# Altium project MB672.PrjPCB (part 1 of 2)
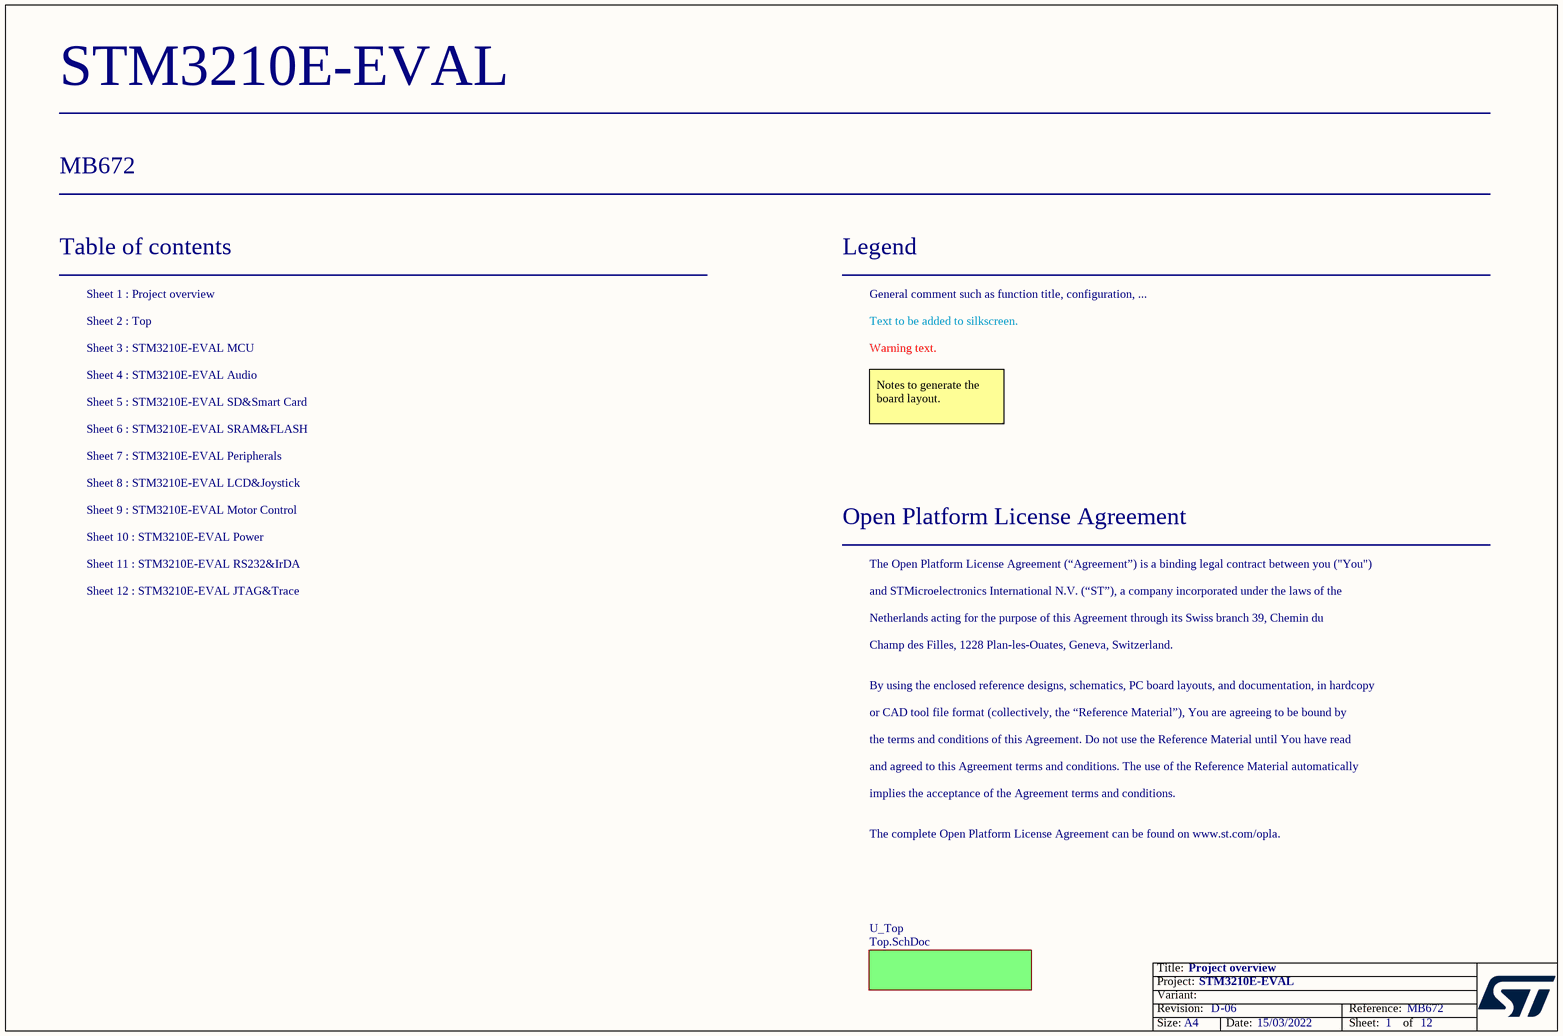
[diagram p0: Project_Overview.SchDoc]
Board_Reference: MB672; Board_PCB_Revision: D; Board_Name: STM3210E-EVAL; Board_Document_Date: 15/03/2022; Board_Assembly_Revision: 06
12 sheets, 357 parts. Net scope: flat (ports and power ports of the same name join across sheets).
Board file: MB672.PCBDOC
Sheets:
  Project_Overview.SchDoc
    U_Top = Top.SchDoc
      U_Audio = Audio.SchDoc
      U_SRAM&Flash = SRAM&Flash.SchDoc
      U_RS232&IrDA = RS232&IrDA.SchDoc
      U_Peripherals = Peripherals.SchDoc
      U_MotorCtrl = MotorCtrl.SchDoc
      U_Power = Power.SchDoc
      U_JTAG&SWD = JTAG&SWD.SchDoc
      U_MCU = MCU.SchDoc
      U_SD&Smart_Card = SD&Smart_Card.SchDoc
      U_LCD&Joystick = LCD&Joystick.SchDoc

## Sheet Project_Overview.SchDoc: Project overview
size A4; Date: Not used; ApprovedBy: Not used; CheckedBy: Not used; Author: Not used; CompanyName: STMicroelectronics; DrawnBy: Not used; Engineer: Not used; Organization: Not used; Address1: Not used; Address2: Not used; Address3: Not used; Address4: Not used; DocumentNumber: Not used; Revision: Not used; SheetNumber: 1; SheetTotal: 12

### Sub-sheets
U_Top = Top.SchDoc: no entries

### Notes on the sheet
- STM3210E-EVAL
- MB672
- Table of contents
- Sheet 1 : Project overview
- Legend
- General comment such as function title, configuration, ...
- Sheet 2 : Top
- Sheet 3 : STM3210E-EVAL MCU
- Sheet 4 : STM3210E-EVAL Audio
- Text to be added to silkscreen.
- Warning text.
- Sheet 6 : STM3210E-EVAL SRAM&FLASH
- Sheet 5 : STM3210E-EVAL SD&Smart Card
- Notes to generate the board layout.
- Sheet 7 : STM3210E-EVAL Peripherals
- Sheet 8 : STM3210E-EVAL LCD&Joystick
- Sheet 9 : STM3210E-EVAL Motor Control
- Sheet 10 : STM3210E-EVAL Power
- Sheet 11 : STM3210E-EVAL RS232&IrDA
- Open Platform License Agreement
- The Open Platform License Agreement (“Agreement”) is a binding legal contract between you ("You")
- Sheet 12 : STM3210E-EVAL JTAG&Trace
- and STMicroelectronics International N.V. (“ST”), a company incorporated under the laws of the
- Netherlands acting for the purpose of this Agreement through its Swiss branch 39, Chemin du
- Champ des Filles, 1228 Plan-les-Ouates, Geneva, Switzerland.
- By using the enclosed reference designs, schematics, PC board layouts, and documentation, in hardcopy
- or CAD tool file format (collectively, the “Reference Material”), You are agreeing to be bound by
- the terms and conditions of this Agreement. Do not use the Reference Material until You have read
- and agreed to this Agreement terms and conditions. The use of the Reference Material automatically
- implies the acceptance of the Agreement terms and conditions.
- The complete Open Platform License Agreement can be found on www.st.com/opla.

## Sheet Top.SchDoc: STM3210E-EVAL
size A3; Date: Not used; ApprovedBy: Not used; CheckedBy: Not used; Author: Not used; CompanyName: STMicroelectronics; DrawnBy: Not used; Engineer: Not used; Organization: Not used; Address1: Not used; Address2: Not used; Address3: Not used; Address4: Not used; DocumentNumber: Not used; Revision: Not used; SheetNumber: 2; SheetTotal: 12
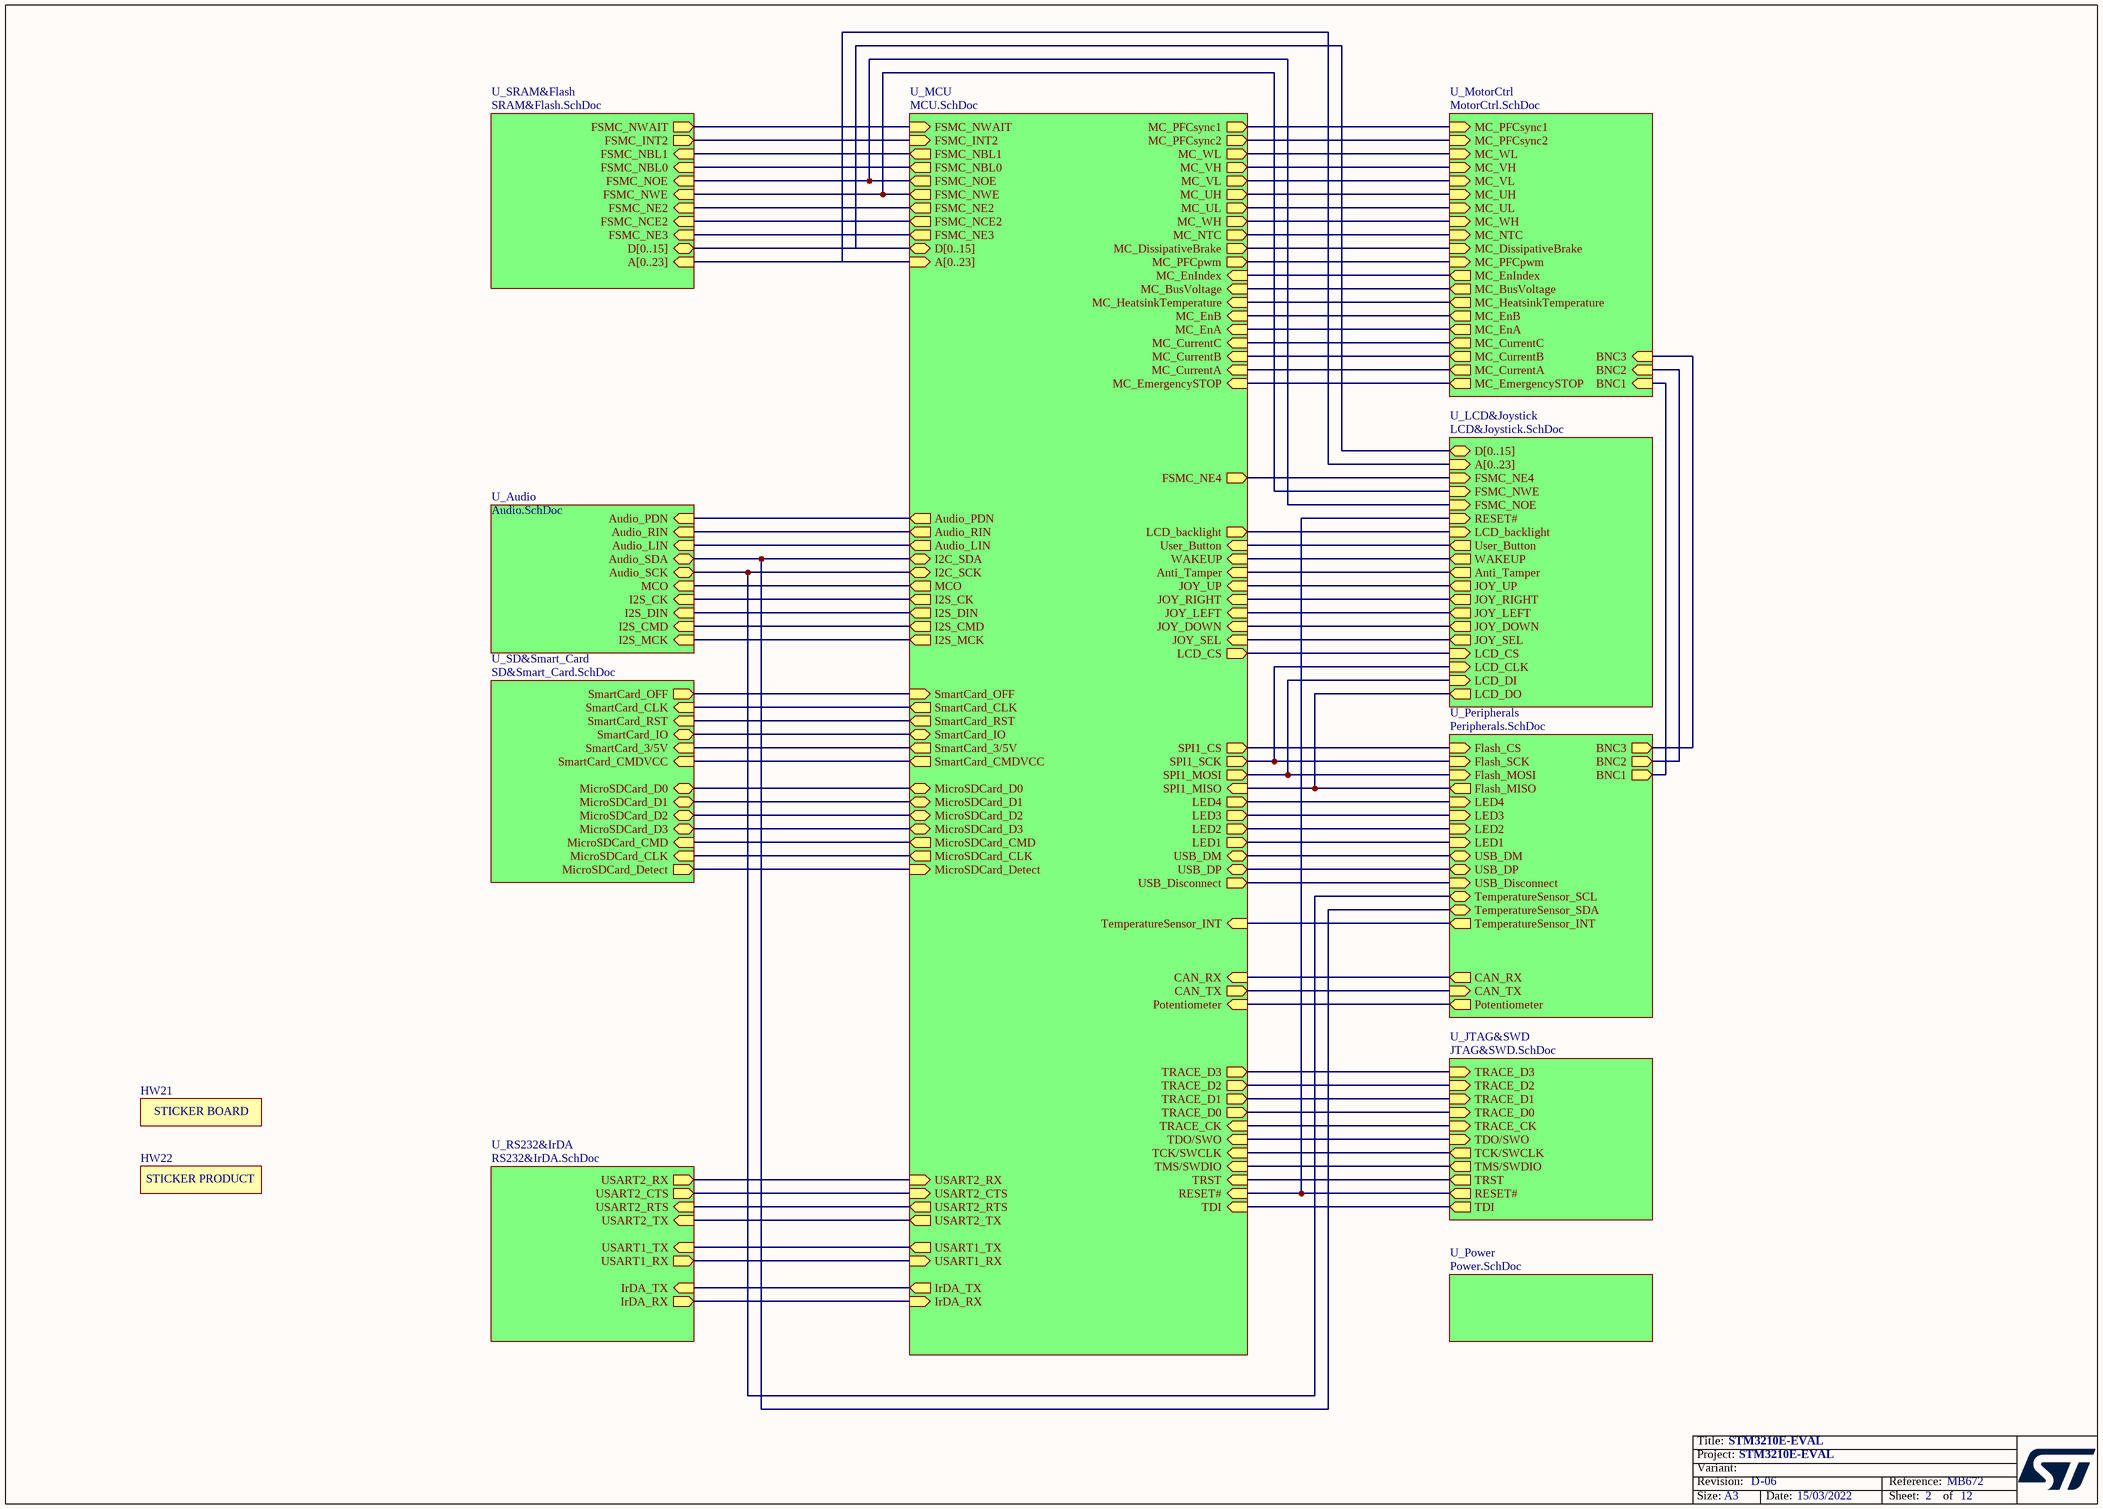
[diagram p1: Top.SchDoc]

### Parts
HW21  STICKER_BOARD  (value not drawn)  (no BOM)
HW22  STICKER_PRODUCT  (value not drawn)  (no BOM)

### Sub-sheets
U_Audio = Audio.SchDoc: I2S_CMD (in), I2S_DIN (in), I2S_CK (in), MCO (in), Audio_SCK (bidir), Audio_SDA (bidir), Audio_LIN (in), Audio_RIN (in), I2S_MCK (in), Audio_PDN (in)
U_JTAG&SWD = JTAG&SWD.SchDoc: TDI (out), RESET# (out), TRACE_D3 (in), TRACE_D2 (in), TRACE_D1 (in), TRACE_D0 (in), TRACE_CK (in), TRST (out), TMS/SWDIO (out), TCK/SWCLK (out), TDO/SWO (in)
U_LCD&Joystick = LCD&Joystick.SchDoc: JOY_SEL (out), JOY_DOWN (out), JOY_LEFT (out), JOY_RIGHT (out), JOY_UP (out), LCD_CS (in), LCD_CLK (in), LCD_DI (in), RESET# (in), LCD_backlight (in), Anti_Tamper (out), WAKEUP (out), User_Button (out), FSMC_NE4 (in), D[0..15] (bidir), A[0..23] (in), FSMC_NWE (in), FSMC_NOE (in), LCD_DO (out)
U_MCU = MCU.SchDoc: TDI (in), TRACE_CK (in), TMS/SWDIO (in), TCK/SWCLK (in), TDO/SWO (in), USART2_RX (in), USART2_TX (out), USART2_RTS (out), USART2_CTS (in), USART1_TX (out), USART1_RX (in), IrDA_RX (in), IrDA_TX (out), MC_EmergencySTOP (in), MC_CurrentA (in), MC_CurrentB (in), MC_CurrentC (in), MC_PFCsync1 (out), MC_PFCsync2 (out), MC_WL (out), MC_VH (out), MC_VL (out), MC_UH (out), MC_UL (out), MC_WH (out), MC_NTC (out), MC_DissipativeBrake (out), MC_PFCpwm (out), MC_EnA (in), MC_EnB (in), MC_HeatsinkTemperature (in), MC_BusVoltage (in), MC_EnIndex (in), JOY_SEL (in), JOY_DOWN (in), JOY_LEFT (in), JOY_RIGHT (in), JOY_UP (in), LCD_CS (out), LCD_backlight (out), Anti_Tamper (in), WAKEUP (in), User_Button (in), SPI1_CS (out), SPI1_SCK (out), SPI1_MISO (in), SPI1_MOSI (out), LED4 (out), LED3 (out), LED1 (out), LED2 (out), USB_DM (bidir), USB_DP (bidir), USB_Disconnect (out), TemperatureSensor_INT (in), CAN_TX (out), CAN_RX (in), Potentiometer (in), FSMC_NE3 (out), A[0..23] (in), D[0..15] (bidir), FSMC_NE4 (out), FSMC_NCE2 (out), FSMC_NE2 (out), FSMC_NWE (out), FSMC_NOE (out), FSMC_NBL0 (out), FSMC_NBL1 (out), FSMC_NWAIT (in), FSMC_INT2 (in), MicroSDCard_CLK (out), MicroSDCard_CMD (out), SmartCard_3/5V (out), SmartCard_IO (bidir), SmartCard_RST (out), SmartCard_CLK (out), SmartCard_OFF (in), SmartCard_CMDVCC (out), MicroSDCard_D0 (bidir), I2S_CMD (out), I2S_DIN (out), I2S_CK (out), MCO (out), I2C_SCK (bidir), I2C_SDA (bidir), MicroSDCard_D1 (bidir), MicroSDCard_D2 (bidir), MicroSDCard_D3 (bidir), RESET# (in), TRACE_D3 (out), TRACE_D2 (out), TRACE_D1 (out), TRACE_D0 (out), TRST (in), Audio_LIN (out), Audio_RIN (out), MicroSDCard_Detect (in), I2S_MCK (out), Audio_PDN (out)
U_MotorCtrl = MotorCtrl.SchDoc: MC_EmergencySTOP (out), MC_CurrentA (out), MC_CurrentB (out), MC_CurrentC (out), MC_PFCsync1 (in), MC_PFCsync2 (in), MC_WL (in), MC_VH (in), MC_VL (in), MC_UH (in), MC_UL (in), MC_WH (in), MC_NTC (in), MC_DissipativeBrake (in), MC_PFCpwm (in), MC_EnA (out), MC_EnB (out), MC_HeatsinkTemperature (out), MC_BusVoltage (out), MC_EnIndex (out), BNC1 (in), BNC2 (in), BNC3 (in)
U_Peripherals = Peripherals.SchDoc: Flash_CS (in), Flash_SCK (in), Flash_MISO (out), Flash_MOSI (in), LED4 (in), LED3 (in), LED1 (in), LED2 (in), USB_DM (bidir), USB_DP (bidir), USB_Disconnect (in), TemperatureSensor_INT (out), TemperatureSensor_SCL (bidir), TemperatureSensor_SDA (bidir), BNC1 (out), CAN_TX (in), CAN_RX (out), Potentiometer (out), BNC2 (out), BNC3 (out)
U_Power = Power.SchDoc: no entries
U_RS232&IrDA = RS232&IrDA.SchDoc: USART2_RX (out), USART2_TX (in), USART2_RTS (in), USART2_CTS (out), USART1_TX (in), USART1_RX (out), IrDA_RX (out), IrDA_TX (in)
U_SD&Smart_Card = SD&Smart_Card.SchDoc: MicroSDCard_CLK (in), MicroSDCard_CMD (in), SmartCard_3/5V (in), SmartCard_IO (bidir), SmartCard_RST (in), SmartCard_CLK (in), SmartCard_OFF (out), SmartCard_CMDVCC (in), MicroSDCard_D0 (bidir), MicroSDCard_D1 (bidir), MicroSDCard_D2 (bidir), MicroSDCard_D3 (bidir), MicroSDCard_Detect (out)
U_SRAM&Flash = SRAM&Flash.SchDoc: A[0..23] (in), D[0..15] (bidir), FSMC_NE3 (in), FSMC_NCE2 (in), FSMC_NE2 (in), FSMC_NWE (in), FSMC_NOE (in), FSMC_NBL0 (in), FSMC_NBL1 (in), FSMC_NWAIT (out), FSMC_INT2 (out)

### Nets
(unnamed): sheet U_Audio/I2S_CMD, sheet U_MCU/I2S_CMD
(unnamed): sheet U_Audio/I2S_DIN, sheet U_MCU/I2S_DIN  [a separate net that carries the same name]
(unnamed): sheet U_Audio/I2S_CK, sheet U_MCU/I2S_CK  [a separate net that carries the same name]
(unnamed): sheet U_Audio/MCO, sheet U_MCU/MCO  [a separate net that carries the same name]
(unnamed): sheet U_Audio/Audio_SCK, sheet U_Peripherals/TemperatureSensor_SCL, sheet U_MCU/I2C_SCK  [a separate net that carries the same name]
(unnamed): sheet U_Audio/Audio_SDA, sheet U_Peripherals/TemperatureSensor_SDA, sheet U_MCU/I2C_SDA  [a separate net that carries the same name]
(unnamed): sheet U_Audio/Audio_LIN, sheet U_MCU/Audio_LIN  [a separate net that carries the same name]
(unnamed): sheet U_Audio/Audio_RIN, sheet U_MCU/Audio_RIN  [a separate net that carries the same name]
(unnamed): sheet U_Audio/I2S_MCK, sheet U_MCU/I2S_MCK  [a separate net that carries the same name]
(unnamed): sheet U_Audio/Audio_PDN, sheet U_MCU/Audio_PDN  [a separate net that carries the same name]
(unnamed): sheet U_SRAM&Flash/FSMC_NE3, sheet U_MCU/FSMC_NE3  [a separate net that carries the same name]
(unnamed): sheet U_SRAM&Flash/FSMC_NCE2, sheet U_MCU/FSMC_NCE2  [a separate net that carries the same name]
(unnamed): sheet U_SRAM&Flash/FSMC_NE2, sheet U_MCU/FSMC_NE2  [a separate net that carries the same name]
(unnamed): sheet U_SRAM&Flash/FSMC_NWE, sheet U_MCU/FSMC_NWE, sheet U_LCD&Joystick/FSMC_NWE  [a separate net that carries the same name]
(unnamed): sheet U_SRAM&Flash/FSMC_NOE, sheet U_MCU/FSMC_NOE, sheet U_LCD&Joystick/FSMC_NOE  [a separate net that carries the same name]
(unnamed): sheet U_SRAM&Flash/FSMC_NBL0, sheet U_MCU/FSMC_NBL0  [a separate net that carries the same name]
(unnamed): sheet U_SRAM&Flash/FSMC_NBL1, sheet U_MCU/FSMC_NBL1  [a separate net that carries the same name]
(unnamed): sheet U_SRAM&Flash/FSMC_NWAIT, sheet U_MCU/FSMC_NWAIT  [a separate net that carries the same name]
(unnamed): sheet U_SRAM&Flash/FSMC_INT2, sheet U_MCU/FSMC_INT2  [a separate net that carries the same name]
(unnamed): sheet U_RS232&IrDA/USART2_RX, sheet U_MCU/USART2_RX  [a separate net that carries the same name]
(unnamed): sheet U_RS232&IrDA/USART2_TX, sheet U_MCU/USART2_TX  [a separate net that carries the same name]
(unnamed): sheet U_RS232&IrDA/USART2_RTS, sheet U_MCU/USART2_RTS  [a separate net that carries the same name]
(unnamed): sheet U_RS232&IrDA/USART2_CTS, sheet U_MCU/USART2_CTS  [a separate net that carries the same name]
(unnamed): sheet U_RS232&IrDA/USART1_TX, sheet U_MCU/USART1_TX  [a separate net that carries the same name]
(unnamed): sheet U_RS232&IrDA/USART1_RX, sheet U_MCU/USART1_RX  [a separate net that carries the same name]
(unnamed): sheet U_RS232&IrDA/IrDA_RX, sheet U_MCU/IrDA_RX  [a separate net that carries the same name]
(unnamed): sheet U_RS232&IrDA/IrDA_TX, sheet U_MCU/IrDA_TX  [a separate net that carries the same name]
(unnamed): sheet U_Peripherals/Flash_CS, sheet U_MCU/SPI1_CS  [a separate net that carries the same name]
(unnamed): sheet U_Peripherals/Flash_SCK, sheet U_MCU/SPI1_SCK, sheet U_LCD&Joystick/LCD_CLK  [a separate net that carries the same name]
(unnamed): sheet U_Peripherals/Flash_MISO, sheet U_MCU/SPI1_MISO, sheet U_LCD&Joystick/LCD_DO  [a separate net that carries the same name]
(unnamed): sheet U_Peripherals/Flash_MOSI, sheet U_MCU/SPI1_MOSI, sheet U_LCD&Joystick/LCD_DI  [a separate net that carries the same name]
(unnamed): sheet U_Peripherals/LED4, sheet U_MCU/LED4  [a separate net that carries the same name]
(unnamed): sheet U_Peripherals/LED3, sheet U_MCU/LED3  [a separate net that carries the same name]
(unnamed): sheet U_Peripherals/LED1, sheet U_MCU/LED1  [a separate net that carries the same name]
(unnamed): sheet U_Peripherals/LED2, sheet U_MCU/LED2  [a separate net that carries the same name]
(unnamed): sheet U_Peripherals/USB_DM, sheet U_MCU/USB_DM  [a separate net that carries the same name]
(unnamed): sheet U_Peripherals/USB_DP, sheet U_MCU/USB_DP  [a separate net that carries the same name]
(unnamed): sheet U_Peripherals/USB_Disconnect, sheet U_MCU/USB_Disconnect  [a separate net that carries the same name]
(unnamed): sheet U_Peripherals/TemperatureSensor_INT, sheet U_MCU/TemperatureSensor_INT  [a separate net that carries the same name]
(unnamed): sheet U_Peripherals/BNC1, sheet U_MotorCtrl/BNC1  [a separate net that carries the same name]
(unnamed): sheet U_Peripherals/CAN_TX, sheet U_MCU/CAN_TX  [a separate net that carries the same name]
(unnamed): sheet U_Peripherals/CAN_RX, sheet U_MCU/CAN_RX  [a separate net that carries the same name]
(unnamed): sheet U_Peripherals/Potentiometer, sheet U_MCU/Potentiometer  [a separate net that carries the same name]
(unnamed): sheet U_Peripherals/BNC2, sheet U_MotorCtrl/BNC2  [a separate net that carries the same name]
(unnamed): sheet U_Peripherals/BNC3, sheet U_MotorCtrl/BNC3  [a separate net that carries the same name]
(unnamed): sheet U_MotorCtrl/MC_EmergencySTOP, sheet U_MCU/MC_EmergencySTOP  [a separate net that carries the same name]
(unnamed): sheet U_MotorCtrl/MC_CurrentA, sheet U_MCU/MC_CurrentA  [a separate net that carries the same name]
(unnamed): sheet U_MotorCtrl/MC_CurrentB, sheet U_MCU/MC_CurrentB  [a separate net that carries the same name]
(unnamed): sheet U_MotorCtrl/MC_CurrentC, sheet U_MCU/MC_CurrentC  [a separate net that carries the same name]
(unnamed): sheet U_MotorCtrl/MC_PFCsync1, sheet U_MCU/MC_PFCsync1  [a separate net that carries the same name]
(unnamed): sheet U_MotorCtrl/MC_PFCsync2, sheet U_MCU/MC_PFCsync2  [a separate net that carries the same name]
(unnamed): sheet U_MotorCtrl/MC_WL, sheet U_MCU/MC_WL  [a separate net that carries the same name]
(unnamed): sheet U_MotorCtrl/MC_VH, sheet U_MCU/MC_VH  [a separate net that carries the same name]
(unnamed): sheet U_MotorCtrl/MC_VL, sheet U_MCU/MC_VL  [a separate net that carries the same name]
(unnamed): sheet U_MotorCtrl/MC_UH, sheet U_MCU/MC_UH  [a separate net that carries the same name]
(unnamed): sheet U_MotorCtrl/MC_UL, sheet U_MCU/MC_UL  [a separate net that carries the same name]
(unnamed): sheet U_MotorCtrl/MC_WH, sheet U_MCU/MC_WH  [a separate net that carries the same name]
(unnamed): sheet U_MotorCtrl/MC_NTC, sheet U_MCU/MC_NTC  [a separate net that carries the same name]
(unnamed): sheet U_MotorCtrl/MC_DissipativeBrake, sheet U_MCU/MC_DissipativeBrake  [a separate net that carries the same name]
(unnamed): sheet U_MotorCtrl/MC_PFCpwm, sheet U_MCU/MC_PFCpwm  [a separate net that carries the same name]
(unnamed): sheet U_MotorCtrl/MC_EnA, sheet U_MCU/MC_EnA  [a separate net that carries the same name]
(unnamed): sheet U_MotorCtrl/MC_EnB, sheet U_MCU/MC_EnB  [a separate net that carries the same name]
(unnamed): sheet U_MotorCtrl/MC_HeatsinkTemperature, sheet U_MCU/MC_HeatsinkTemperature  [a separate net that carries the same name]
(unnamed): sheet U_MotorCtrl/MC_BusVoltage, sheet U_MCU/MC_BusVoltage  [a separate net that carries the same name]
(unnamed): sheet U_MotorCtrl/MC_EnIndex, sheet U_MCU/MC_EnIndex  [a separate net that carries the same name]
(unnamed): sheet U_JTAG&SWD/TDI, sheet U_MCU/TDI  [a separate net that carries the same name]
(unnamed): sheet U_JTAG&SWD/RESET#, sheet U_MCU/RESET#, sheet U_LCD&Joystick/RESET#  [a separate net that carries the same name]
(unnamed): sheet U_JTAG&SWD/TRACE_D3, sheet U_MCU/TRACE_D3  [a separate net that carries the same name]
(unnamed): sheet U_JTAG&SWD/TRACE_D2, sheet U_MCU/TRACE_D2  [a separate net that carries the same name]
(unnamed): sheet U_JTAG&SWD/TRACE_D1, sheet U_MCU/TRACE_D1  [a separate net that carries the same name]
(unnamed): sheet U_JTAG&SWD/TRACE_D0, sheet U_MCU/TRACE_D0  [a separate net that carries the same name]
(unnamed): sheet U_JTAG&SWD/TRACE_CK, sheet U_MCU/TRACE_CK  [a separate net that carries the same name]
(unnamed): sheet U_JTAG&SWD/TRST, sheet U_MCU/TRST  [a separate net that carries the same name]
(unnamed): sheet U_JTAG&SWD/TMS/SWDIO, sheet U_MCU/TMS/SWDIO  [a separate net that carries the same name]
(unnamed): sheet U_JTAG&SWD/TCK/SWCLK, sheet U_MCU/TCK/SWCLK  [a separate net that carries the same name]
(unnamed): sheet U_JTAG&SWD/TDO/SWO, sheet U_MCU/TDO/SWO  [a separate net that carries the same name]
(unnamed): sheet U_MCU/JOY_SEL, sheet U_LCD&Joystick/JOY_SEL  [a separate net that carries the same name]
(unnamed): sheet U_MCU/JOY_DOWN, sheet U_LCD&Joystick/JOY_DOWN  [a separate net that carries the same name]
(unnamed): sheet U_MCU/JOY_LEFT, sheet U_LCD&Joystick/JOY_LEFT  [a separate net that carries the same name]
(unnamed): sheet U_MCU/JOY_RIGHT, sheet U_LCD&Joystick/JOY_RIGHT  [a separate net that carries the same name]
(unnamed): sheet U_MCU/JOY_UP, sheet U_LCD&Joystick/JOY_UP  [a separate net that carries the same name]
(unnamed): sheet U_MCU/LCD_CS, sheet U_LCD&Joystick/LCD_CS  [a separate net that carries the same name]
(unnamed): sheet U_MCU/LCD_backlight, sheet U_LCD&Joystick/LCD_backlight  [a separate net that carries the same name]
(unnamed): sheet U_MCU/Anti_Tamper, sheet U_LCD&Joystick/Anti_Tamper  [a separate net that carries the same name]
(unnamed): sheet U_MCU/WAKEUP, sheet U_LCD&Joystick/WAKEUP  [a separate net that carries the same name]
(unnamed): sheet U_MCU/User_Button, sheet U_LCD&Joystick/User_Button  [a separate net that carries the same name]
(unnamed): sheet U_MCU/FSMC_NE4, sheet U_LCD&Joystick/FSMC_NE4  [a separate net that carries the same name]
(unnamed): sheet U_MCU/MicroSDCard_CLK, sheet U_SD&Smart_Card/MicroSDCard_CLK  [a separate net that carries the same name]
(unnamed): sheet U_MCU/MicroSDCard_CMD, sheet U_SD&Smart_Card/MicroSDCard_CMD  [a separate net that carries the same name]
(unnamed): sheet U_MCU/SmartCard_3/5V, sheet U_SD&Smart_Card/SmartCard_3/5V  [a separate net that carries the same name]
(unnamed): sheet U_MCU/SmartCard_IO, sheet U_SD&Smart_Card/SmartCard_IO  [a separate net that carries the same name]
(unnamed): sheet U_MCU/SmartCard_RST, sheet U_SD&Smart_Card/SmartCard_RST  [a separate net that carries the same name]
(unnamed): sheet U_MCU/SmartCard_CLK, sheet U_SD&Smart_Card/SmartCard_CLK  [a separate net that carries the same name]
(unnamed): sheet U_MCU/SmartCard_OFF, sheet U_SD&Smart_Card/SmartCard_OFF  [a separate net that carries the same name]
(unnamed): sheet U_MCU/SmartCard_CMDVCC, sheet U_SD&Smart_Card/SmartCard_CMDVCC  [a separate net that carries the same name]
(unnamed): sheet U_MCU/MicroSDCard_D0, sheet U_SD&Smart_Card/MicroSDCard_D0  [a separate net that carries the same name]
(unnamed): sheet U_MCU/MicroSDCard_D1, sheet U_SD&Smart_Card/MicroSDCard_D1  [a separate net that carries the same name]
(unnamed): sheet U_MCU/MicroSDCard_D2, sheet U_SD&Smart_Card/MicroSDCard_D2  [a separate net that carries the same name]
(unnamed): sheet U_MCU/MicroSDCard_D3, sheet U_SD&Smart_Card/MicroSDCard_D3  [a separate net that carries the same name]
(unnamed): sheet U_MCU/MicroSDCard_Detect, sheet U_SD&Smart_Card/MicroSDCard_Detect  [a separate net that carries the same name]

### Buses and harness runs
bus sheet U_LCD&Joystick/A[0..23] = sheet U_MCU/A[0..23] = sheet U_SRAM&Flash/A[0..23]
bus sheet U_LCD&Joystick/D[0..15] = sheet U_MCU/D[0..15] = sheet U_SRAM&Flash/D[0..15]

## Sheet Audio.SchDoc: STM3210E-EVAL Audio
size A4; Date: Not used; ApprovedBy: Not used; CheckedBy: Not used; Author: Not used; CompanyName: STMicroelectronics; DrawnBy: Not used; Engineer: Not used; Organization: Not used; Address1: Not used; Address2: Not used; Address3: Not used; Address4: Not used; DocumentNumber: Not used; Revision: Not used; SheetNumber: 4; SheetTotal: 12
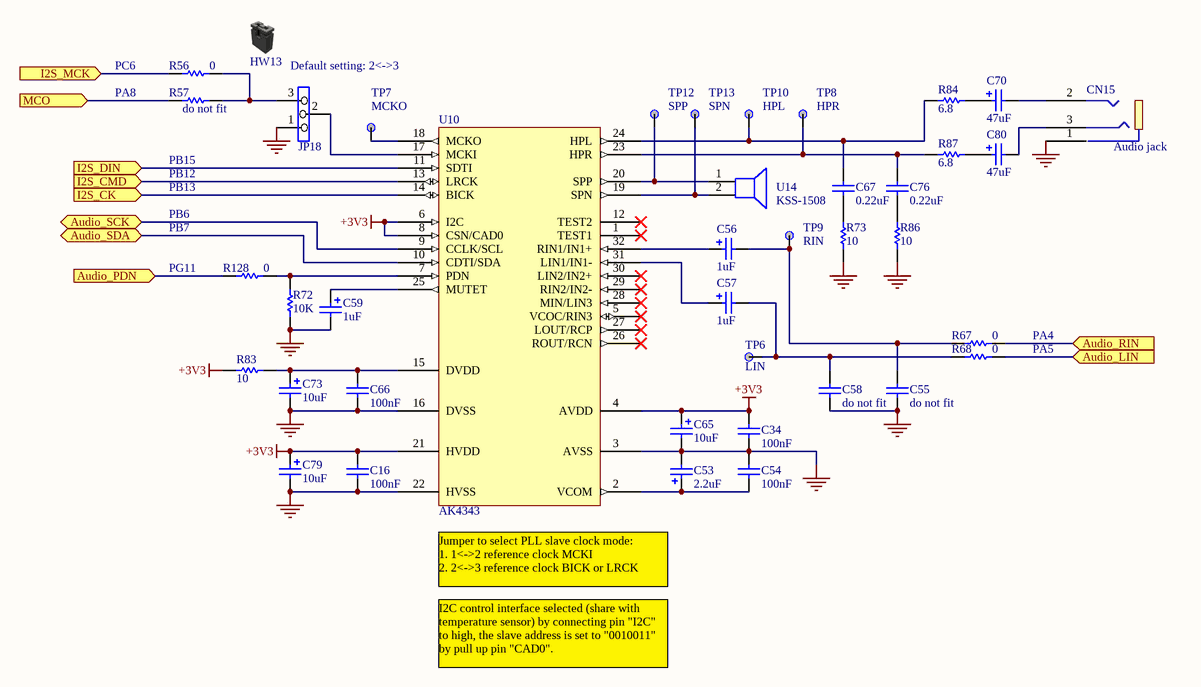
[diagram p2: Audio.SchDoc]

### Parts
C16  100nF  [0603P]
C34  100nF  [0603P]
C53  2.2uF  [C160M]
C54  100nF  [0603P]
C55  do not fit  [0603P]
C56  1uF  [C160M]
C57  1uF  [C160M]
C58  do not fit  [0603P]
C59  1uF  [C160M]
C65  10uF  [C160M]
C66  100nF  [0603P]
C67  0.22uF  [0603P]
C70  47uF  [C160M]
C73  10uF  [C160M]
C76  0.22uF  [0603P]
C79  10uF  [C160M]
C80  47uF  [C160M]
CN15  Audio jack
HW13  Shunt Black 2.54mm  (value not drawn)  (mechanical)
JP18  (no value)  [SIP3]
R56  0  [0603]
R57  do not fit  [0603]
R67  0  [0603]
R68  0  [0603]
R72  10K  [0603]
R73  10  [0603]
R83  10  [0603]
R84  6.8  [0603]
R86  10  [0603]
R87  6.8  [0603]
R128  0  [0603]
TP6  LIN  [TP]
TP7  MCKO  [TP]
TP8  HPR  [TP]
TP9  RIN  [TP]
TP10  HPL  [TP]
TP12  SPP  [TP]
TP13  SPN  [TP]
U10  AK4343  [QFN32]
U14  KSS-1508  [KS1508]

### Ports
Audio_LIN (in), Audio_PDN (in), Audio_RIN (in), Audio_SCK (bidir), Audio_SDA (bidir), I2S_CK (in), I2S_CMD (in), I2S_DIN (in), I2S_MCK (in), MCO (in)

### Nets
+3V3: C16.1 C34.2 C65.1 C79.1 R83.2 U10.4(AVDD) U10.6(I2C) U10.8(CSN/CAD0) U10.21(HVDD)
GND: C16.2 C34.1 C53.2 C54.2 C55.1 C58.1 C59.2 C65.2 C66.2 C73.2 C79.2 CN15.1 JP18.1 R72.2 R73.2 R86.2 U10.3(AVSS) U10.16(DVSS) U10.22(HVSS)
PA4: R67.2 ; port Audio_RIN
PA5: R68.2 ; port Audio_LIN
PA8: R57.2 ; port MCO
PB12: U10.13(LRCK) ; port I2S_CMD
PB13: U10.14(BICK) ; port I2S_CK
PB15: U10.11(SDTI) ; port I2S_DIN
PC6: R56.2 ; port I2S_MCK
PG11: R128.2 ; port Audio_PDN
NetC53_1: C53.1 C54.1 U10.2(VCOM)
NetC55_2: C55.2 C56.2 R67.1 TP9.1
NetC56_1: C56.1 U10.32(RIN1/IN1+)
NetC57_1: C57.1 U10.31(LIN1/IN1-)
NetC57_2: C57.2 C58.2 R68.1 TP6.1
NetC59_1: C59.1 U10.25(MUTET)
NetC66_1: C66.1 C73.1 R83.1 U10.15(DVDD)
NetC67_1: C67.1 R84.2 TP10.1 U10.24(HPL)
NetC67_2: C67.2 R73.1
NetC70_1: C70.1 R84.1
NetC70_2: C70.2 CN15.2
NetC76_1: C76.1 R87.2 TP8.1 U10.23(HPR)
NetC76_2: C76.2 R86.1
NetC80_1: C80.1 R87.1
NetC80_2: C80.2 CN15.3
NetJP18_2: JP18.2 U10.17(MCKI)
NetJP18_3: JP18.3 R56.1 R57.1
NetR72_1: R72.1 R128.1 U10.7(PDN)
NetTP7_1: TP7.1 U10.18(MCKO)
NetTP12_1: TP12.1 U10.20(SPP) U14.1(+)
NetTP13_1: TP13.1 U10.19(SPN) U14.2(-)
NetU10_9: U10.9(CCLK/SCL) ; port Audio_SCK
NetU10_10: U10.10(CDTI/SDA) ; port Audio_SDA

Not connected (* = marked no-connect by the designer): U10 1(TEST1)* 5(VCOC/RIN3)* 12(TEST2)* 26(ROUT/RCN)* 27(LOUT/RCP)* 28(MIN/LIN3)* 29(RIN2/IN2-)* 30(LIN2/IN2+)*

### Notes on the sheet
- PC6
- (near JP18) Default setting: 2<->3
- PA8
- PB12
- PB13
- PB15
- PB6
- PB7
- (near R128) PG11
- PA5
- PA4
- Jumper to select PLL slave clock mode:
  1. 1<->2 reference clock MCKI
  2. 2<->3 reference clock BICK or LRCK
- I2C control interface selected (share with temperature sensor) by connecting pin "I2C" to high, the slave address is set to "0010011"  by pull up pin "CAD0".

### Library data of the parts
C16 C34 C54 C66 = CAP: Capacitor
C53 C56 C57 C59 C65 C73 C79 = Cap Pol1: Polarized Capacitor (Radial); Value: 47uF
C55 C58 C67 C76 = CAP: Capacitor; Value: 100nF
C70 C80 = Cap Pol1: Polarized Capacitor (Radial)
CN15 = ST-225-02
JP18 = Jumper3
R56 R57 R67 R68 R72 R73 R83 R84 R86 R87 R128 = res1: Resistor; Value: 1K
TP6-TP10 TP12 TP13 = TP
U14 = Speaker: Loudspeaker

## Sheet SRAM&Flash.SchDoc: STM3210E-EVAL SRAM&FLASH
size A4; Date: Not used; ApprovedBy: Not used; CheckedBy: Not used; Author: Not used; CompanyName: STMicroelectronics; DrawnBy: Not used; Engineer: Not used; Organization: Not used; Address1: Not used; Address2: Not used; Address3: Not used; Address4: Not used; DocumentNumber: Not used; Revision: Not used; SheetNumber: 6; SheetTotal: 12
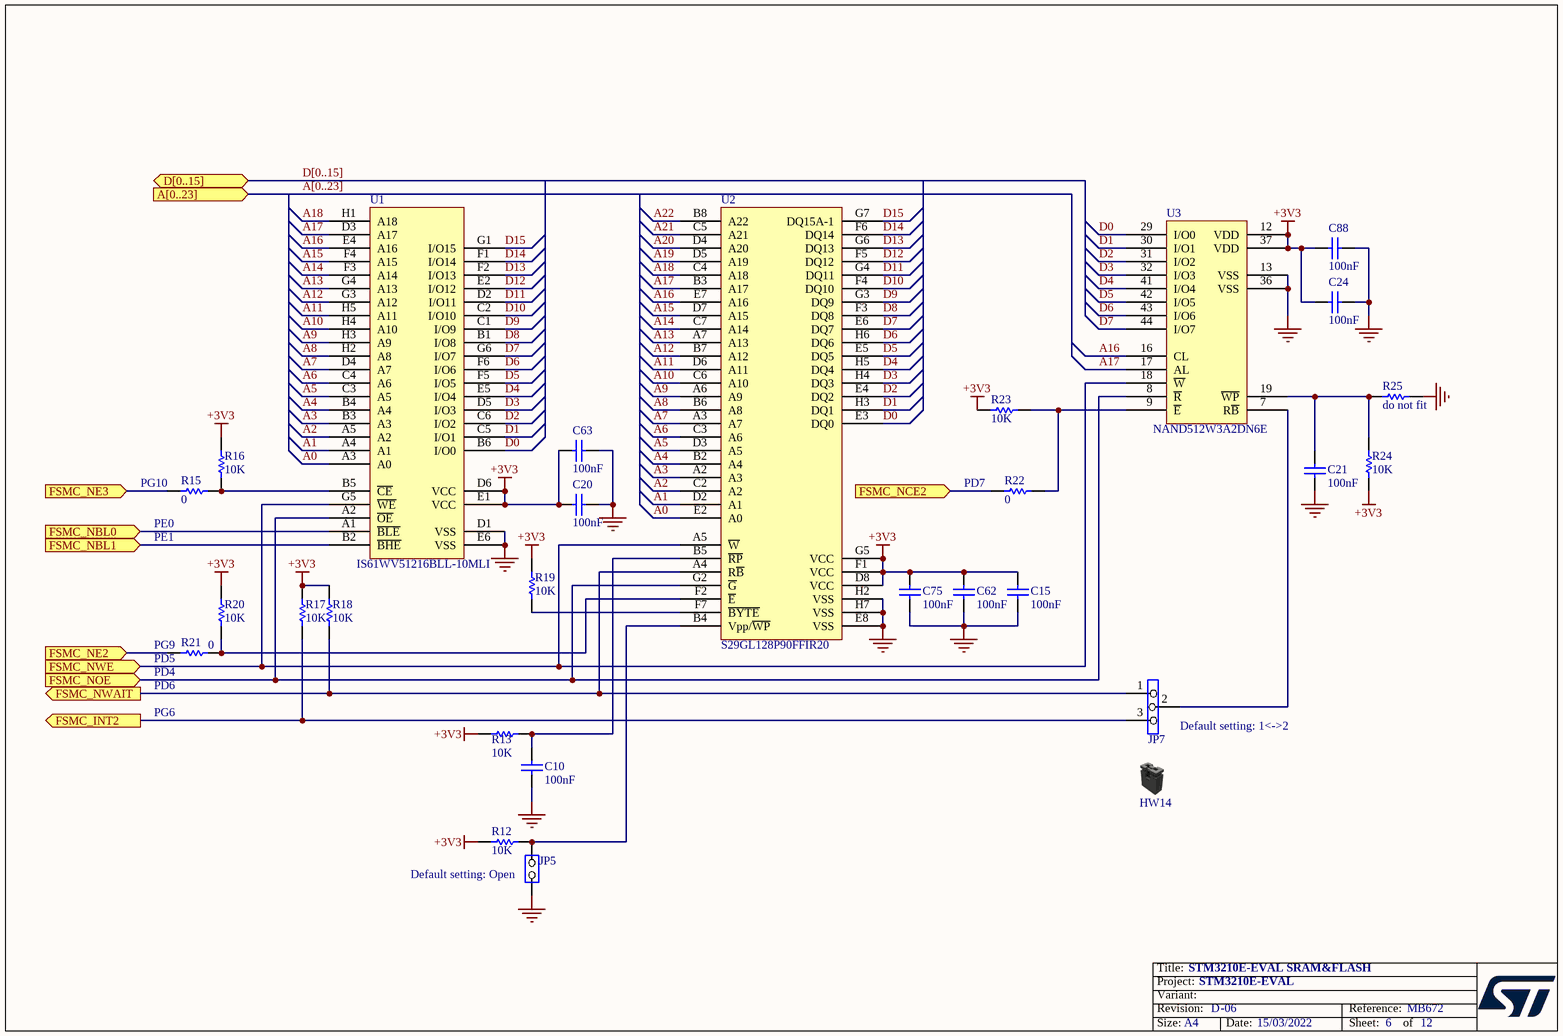
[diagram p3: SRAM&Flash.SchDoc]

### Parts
C10  100nF  [0603]
C15  100nF  [0603]
C20  100nF  [0603]
C21  100nF  [0603]
C24  100nF  [0603]
C62  100nF  [0603]
C63  100nF  [0603]
C75  100nF  [0603]
C88  100nF  [0603]
HW14  Shunt Black 2.54mm  (value not drawn)  (mechanical)
JP5  (no value)  [SIP2]
JP7  (no value)  [SIP3]
R12  10K  [0603]
R13  10K  [0603]
R15  0  [0603]
R16  10K  [0603]
R17  10K  [0603]
R18  10K  [0603]
R19  10K  [0603]
R20  10K  [0603]
R21  0  [0603]
R22  0  [0603]
R23  10K  [0603]
R24  10K  [0603]
R25  do not fit  [0603]
U1  IS61WV51216BLL-10MLI  [FBGA48]
U2  (no value)  [TBGA64(10x13)]
U3  NAND512W3A2DN6E  [TSOP48]

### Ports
A[0..23] (in), D[0..15] (bidir), FSMC_INT2 (out), FSMC_NBL0 (in), FSMC_NBL1 (in), FSMC_NCE2 (in), FSMC_NE2 (in), FSMC_NE3 (in), FSMC_NOE (in), FSMC_NWAIT (out), FSMC_NWE (in)

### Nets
+3V3: C15.2 C20.2 C24.2 C62.2 C63.2 C75.2 C88.2 R12.1 R13.2 R16.1 R17.2 R18.2 R19.1 R20.2 R23.2 R24.1 U1.D6(VCC) U1.E1(VCC) U2.D8(VCC) U2.F1(VCC) U2.G5(VCC) U3.12(VDD) U3.37(VDD)
GND: C10.2 C15.1 C20.1 C21.1 C24.1 C62.1 C63.1 C75.1 C88.1 JP5.1(COMMON) R25.2 U1.D1(VSS) U1.E6(VSS) U2.E8(VSS) U2.H2(VSS) U2.H7(VSS) U3.13(VSS) U3.36(VSS)
A0: U1.A3(A0) U2.E2(A0)
A1: U1.A4(A1) U2.D2(A1)
A2: U1.A5(A2) U2.C2(A2)
A3: U1.B3(A3) U2.A2(A3)
A4: U1.B4(A4) U2.B2(A4)
A5: U1.C3(A5) U2.D3(A5)
A6: U1.C4(A6) U2.C3(A6)
A7: U1.D4(A7) U2.A3(A7)
A8: U1.H2(A8) U2.B6(A8)
A9: U1.H3(A9) U2.A6(A9)
A10: U1.H4(A10) U2.C6(A10)
A11: U1.H5(A11) U2.D6(A11)
A12: U1.G3(A12) U2.B7(A12)
A13: U1.G4(A13) U2.A7(A13)
A14: U1.F3(A14) U2.C7(A14)
A15: U1.F4(A15) U2.D7(A15)
A16: U1.E4(A16) U2.E7(A16) U3.16(CL)
A17: U1.D3(A17) U2.B3(A17) U3.17(AL)
A18: U1.H1(A18) U2.C4(A18)
A19: U2.D5(A19)
A20: U2.D4(A20)
A21: U2.C5(A21)
A22: U2.B8(A22)
D0: U1.B6(I/O0) U2.E3(DQ0) U3.29(I/O0)
D1: U1.C5(I/O1) U2.H3(DQ1) U3.30(I/O1)
D2: U1.C6(I/O2) U2.E4(DQ2) U3.31(I/O2)
D3: U1.D5(I/O3) U2.H4(DQ3) U3.32(I/O3)
D4: U1.E5(I/O4) U2.H5(DQ4) U3.41(I/O4)
D5: U1.F5(I/O5) U2.E5(DQ5) U3.42(I/O5)
D6: U1.F6(I/O6) U2.H6(DQ6) U3.43(I/O6)
D7: U1.G6(I/O7) U2.E6(DQ7) U3.44(I/O7)
D8: U1.B1(I/O8) U2.F3(DQ8)
D9: U1.C1(I/O9) U2.G3(DQ9)
D10: U1.C2(I/O10) U2.F4(DQ10)
D11: U1.D2(I/O11) U2.G4(DQ11)
D12: U1.E2(I/O12) U2.F5(DQ12)
D13: U1.F2(I/O13) U2.G6(DQ13)
D14: U1.F1(I/O14) U2.F6(DQ14)
D15: U1.G1(I/O15) U2.G7(DQ15A-1)
PD4: U1.A2(~{OE}) U2.G2(~{G}) U3.8(~{R}) ; port FSMC_NOE
PD5: U1.G5(~{WE}) U2.A5(~{W}) U3.18(~{W}) ; port FSMC_NWE
PD6: JP7.1 R18.1 U2.A4(R~{B}) ; port FSMC_NWAIT
PD7: R22.1 ; port FSMC_NCE2
PE0: U1.A1(~{BLE}) ; port FSMC_NBL0
PE1: U1.B2(~{BHE}) ; port FSMC_NBL1
PG6: JP7.3 R17.1 ; port FSMC_INT2
PG9: R21.1 ; port FSMC_NE2
PG10: R15.1 ; port FSMC_NE3
NetC10_1: C10.1 R13.1 U2.B5(~{RP})
NetC21_2: C21.2 R24.2 R25.1 U3.19(~{WP})
NetJP5_2: JP5.2(NO) R12.2 U2.B4(Vpp/~{WP})
NetJP7_2: JP7.2 U3.7(R~{B})
NetR15_2: R15.2 R16.2 U1.B5(~{CE})
NetR19_2: R19.2 U2.F7(~{BYTE})
NetR20_1: R20.1 R21.2 U2.F2(~{E})
NetR22_2: R22.2 R23.1 U3.9(~{E})

Not connected (* = marked no-connect by the designer): U3 1(NC) 2(NC) 3(NC) 4(NC) 5(NC) 6(NC) 10(NC) 11(NC) 14(NC) 15(NC) 20(NC) 21(NC) 22(NC) 23(NC) 24(NC) 25(NC) 26(NC) 27(NC) 28(NC) 33(NC) 34(NC) 35(NC) 38(NC) 39(NC) 40(NC) 45(NC) 46(NC) 47(NC) 48(NC)

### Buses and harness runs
bus A[0..23] = port A[0..23]
bus D[0..15] = port D[0..15]

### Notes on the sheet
- (near R15) PG10
- (near R22) PD7
- (near R15) PE1
- (near R15) PE0
- (near R21) PG9
- (near U2) S29GL128P90FFIR20
- (near R21) PD5
- (near R21) PD6
- (near R21) PD4
- PG6
- (near JP7) Default setting: 1<->2
- (near JP5) Default setting: Open

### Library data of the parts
C10 C15 C20 C21 C24 C62 C63 C75 C88 = cap: Capacitor; Value: 100pF
JP5 = JP2
JP7 = Jumper3
R12 R13 R15-R25 = Res1: Resistor; Value: 1K
U1 = IS64WV51216BLL-10MA3
U2 = M29W128FL70ZA6E
U3 = NAND01GW3B2BN: 1G/8bits/3.3V/large page/

## Sheet RS232&IrDA.SchDoc: STM3210E-EVAL RS232&IrDA
size A4; Date: Not used; ApprovedBy: Not used; CheckedBy: Not used; Author: Not used; CompanyName: STMicroelectronics; DrawnBy: Not used; Engineer: Not used; Organization: Not used; Address1: Not used; Address2: Not used; Address3: Not used; Address4: Not used; DocumentNumber: Not used; Revision: Not used; SheetNumber: 11; SheetTotal: 12
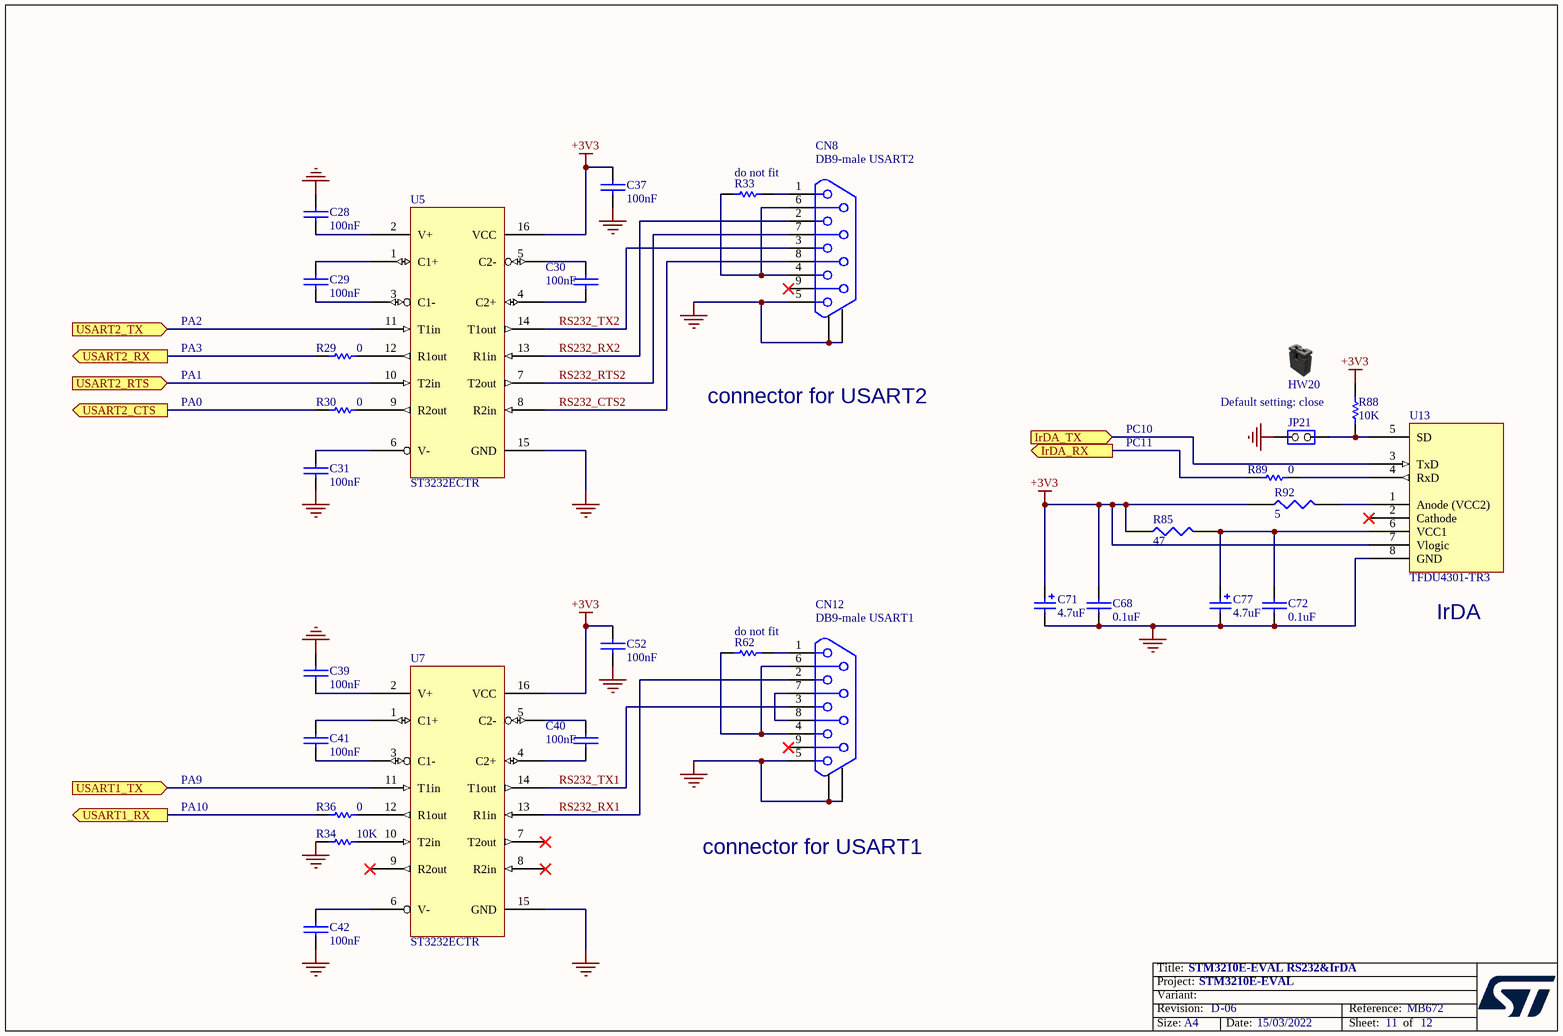
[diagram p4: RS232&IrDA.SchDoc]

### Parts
C28  100nF  [0603P]
C29  100nF  [0603P]
C30  100nF  [0603P]
C31  100nF  [0603P]
C37  100nF  [0603P]
C39  100nF  [0603P]
C40  100nF  [0603P]
C41  100nF  [0603P]
C42  100nF  [0603P]
C52  100nF  [0603P]
C68  0.1uF  [0603P]
C71  4.7uF  [TAN-B]
C72  0.1uF  [0603P]
C77  4.7uF  [TAN-B]
CN8  DB9-male USART2  [DB9/M]
CN12  DB9-male USART1  [DB9/M]
HW20  Shunt Black 2.54mm  (value not drawn)  (mechanical)
JP21  (no value)  [SIP2]
R29  0  [0805]
R30  0  [0805]
R33  do not fit  [0603_NC]
R34  10K  [0603]
R36  0  [0805]
R62  do not fit  [0603_NC]
R85  47  [0603]
R88  10K  [0603]
R89  0  [0805]
R92  5  [0603]
U5  ST3232ECTR  [TSSOP16]
U7  ST3232ECTR  [TSSOP16]
U13  TFDU4301-TR3  [IR_VISHAY3]

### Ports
IrDA_RX (out), IrDA_TX (in), USART1_RX (out), USART1_TX (in), USART2_CTS (out), USART2_RTS (in), USART2_RX (out), USART2_TX (in)

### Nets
+3V3: C37.1 C52.1 C68.1 C71.1 R85.1 R88.2 R92.1 U5.16(VCC) U7.16(VCC) U13.7(Vlogic)
GND: C28.1 C31.1 C37.2 C39.1 C42.1 C52.2 C68.2 C71.2 C72.2 C77.2 CN8.0 CN8.5 CN12.0 CN12.5 JP21.2(NO) R34.2 U5.15(GND) U7.15(GND) U13.8(GND)
PA1: U5.10(T2in) ; port USART2_RTS
PA2: U5.11(T1in) ; port USART2_TX
PA9: U7.11(T1in) ; port USART1_TX
PA10: R36.2 ; port USART1_RX
PC10: U13.3(TxD) ; port IrDA_TX
RS232_CTS2: CN8.8 U5.8(R2in)
RS232_RTS2: CN8.7 U5.7(T2out)
RS232_RX1: CN12.2 U7.13(R1in)
RS232_RX2: CN8.2 U5.13(R1in)
RS232_TX1: CN12.3 U7.14(T1out)
RS232_TX2: CN8.3 U5.14(T1out)
NetC28_2: C28.2 U5.2(V+)
NetC29_1: C29.1 U5.1(C1+)
NetC29_2: C29.2 U5.3(C1-)
NetC30_1: C30.1 U5.4(C2+)
NetC30_2: C30.2 U5.5(C2-)
NetC31_2: C31.2 U5.6(V-)
NetC39_2: C39.2 U7.2(V+)
NetC40_1: C40.1 U7.4(C2+)
NetC40_2: C40.2 U7.5(C2-)
NetC41_1: C41.1 U7.1(C1+)
NetC41_2: C41.2 U7.3(C1-)
NetC42_2: C42.2 U7.6(V-)
NetC72_1: C72.1 C77.1 R85.2 U13.6(VCC1)
NetCN8_1: CN8.1 R33.2
NetCN8_4: CN8.4 CN8.6 R33.1
NetCN12_1: CN12.1 R62.2
NetCN12_4: CN12.4 CN12.6 R62.1
NetCN12_7: CN12.7 CN12.8
NetJP4_3: R30.2 ; port USART2_CTS
NetJP21_1: JP21.1(COMMON) R88.1 U13.5(SD)
NetJP22_2: R89.2 ; port IrDA_RX
NetR29_1: R29.1 U5.12(R1out)
NetR29_2: R29.2 ; port USART2_RX
NetR30_1: R30.1 U5.9(R2out)
NetR34_1: R34.1 U7.10(T2in)
NetR36_1: R36.1 U7.12(R1out)
NetR89_1: R89.1 U13.4(RxD)
NetR92_2: R92.2 U13.1(Anode_(VCC2))

Not connected (* = marked no-connect by the designer): CN8 9*; CN12 9*; U7 7(T2out)* 8(R2in)* 9(R2out)*; U13 2(Cathode)*

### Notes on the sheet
- PA1
- PA2
- PA3
- PA0
- connector for USART2
- PC10
- PC11
- (near R88) Default setting: close
- (near U13) IrDA
- PA9
- PA10
- connector for USART1

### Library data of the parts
C28-C31 C37 C39-C42 C52 C68 C72 = CAP: Capacitor
C71 C77 = Cap Pol1: Polarized Capacitor (Radial); Value: 100pF
CN8 CN12 = DB9
JP21 = JP2
R29 R30 R34 R36 R88 R89 = Res1: Resistor; Value: 1K
R33 R62 = res1: Resistor; Value: 1K
R85 R92 = RES1
U5 U7 = ST3232: 3.3V/5V Dual RS232 Transceiver w/ Int. Cap.
U13 = TFDU4300

## Sheet Peripherals.SchDoc: STM3210E-EVAL Peripherals
size A4; Date: Not used; ApprovedBy: Not used; CheckedBy: Not used; Author: Not used; CompanyName: STMicroelectronics; DrawnBy: Not used; Engineer: Not used; Organization: Not used; Address1: Not used; Address2: Not used; Address3: Not used; Address4: Not used; DocumentNumber: Not used; Revision: Not used; SheetNumber: 7; SheetTotal: 12
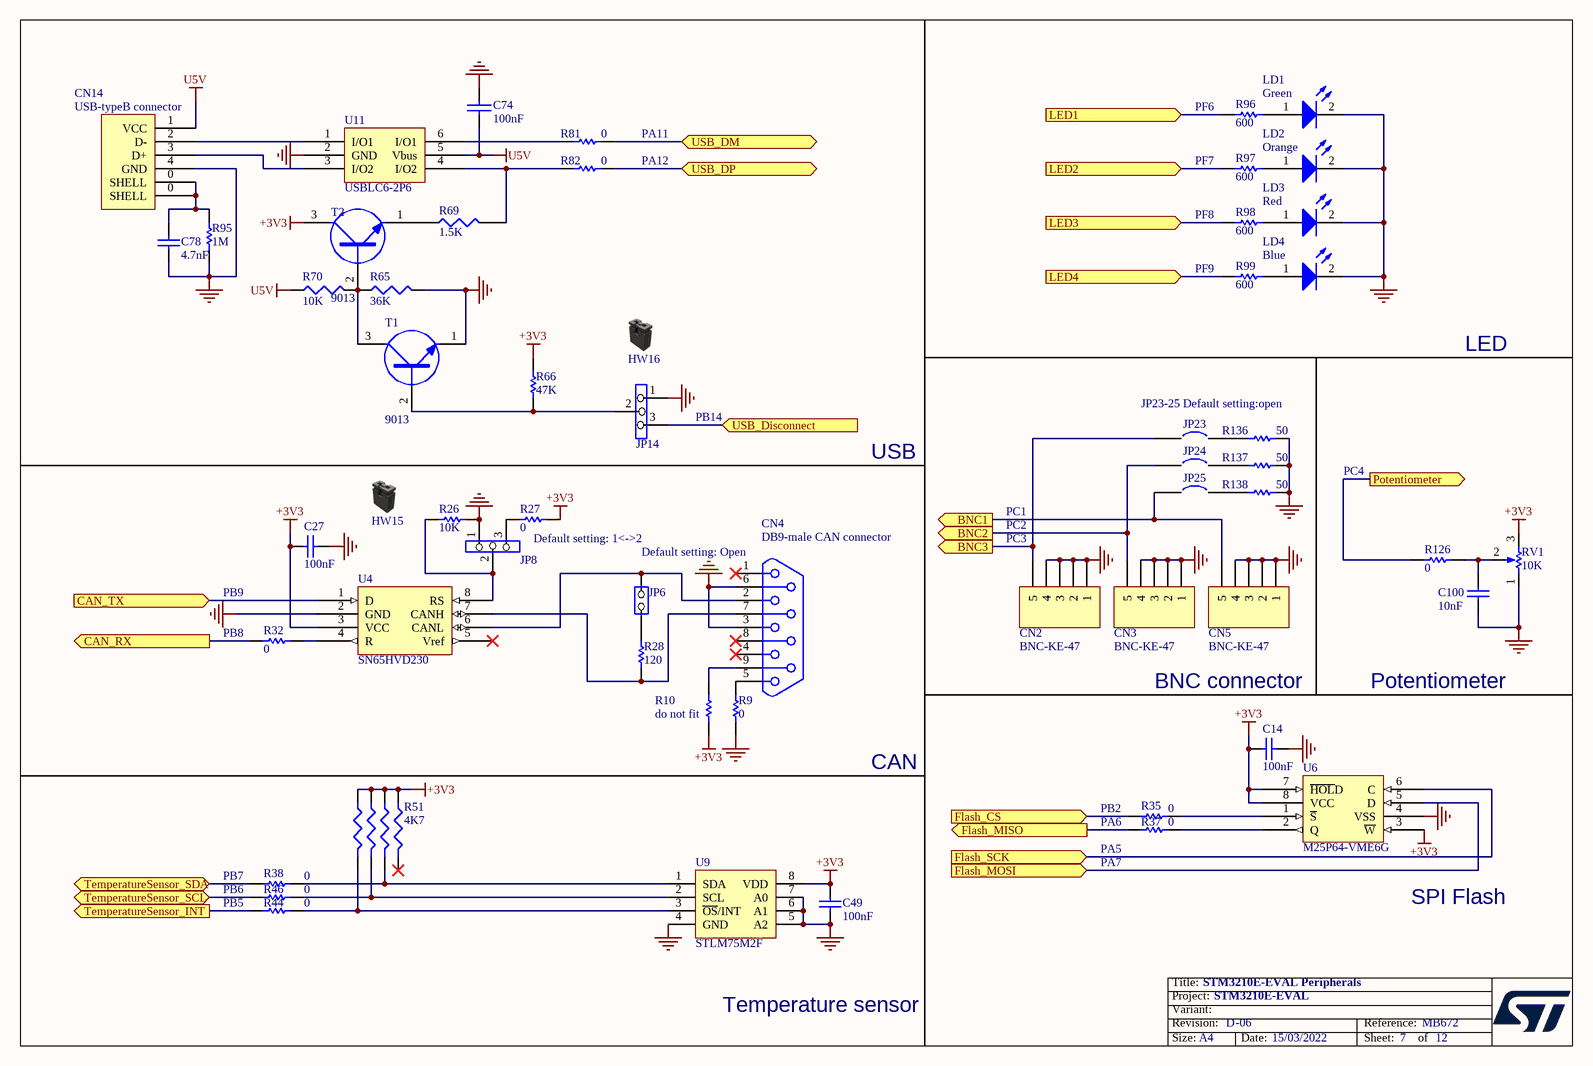
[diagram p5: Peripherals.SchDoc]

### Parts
C14  100nF  [0603P]
C27  100nF  [0603P]
C49  100nF  [0603P]
C74  100nF  [0603P]
C78  4.7nF  [0603]
C100  10nF  [0603]
CN2  BNC-KE-47  [VB334]
CN3  BNC-KE-47  [VB334]
CN4  DB9-male CAN connector  [DB9/M]
CN5  BNC-KE-47  [VB334]
CN14  USB-typeB connector  [USB-B]
HW15  Shunt Black 2.54mm  (value not drawn)  (mechanical)
HW16  Shunt Black 2.54mm  (value not drawn)  (mechanical)
JP6  (no value)  [SIP2]
JP8  (no value)  [SIP3]
JP14  (no value)  [SIP3]
JP23  (no value)  [SPST-2]
JP24  (no value)  [SPST-2]
JP25  (no value)  [SPST-2]
LD1  Green  [D0603]
LD2  Orange  [D0603]
LD3  Red  [D0603]
LD4  Blue  [D0603]
R9  0  [0603]
R10  do not fit  [0603]
R26  10K  [0603]
R27  0  [0603]
R28  120  [0603]
R32  0  [0805]
R35  0  [0805]
R37  0  [0805]
R38  0  [0805]
R44  0  [0805]
R46  0  [0805]
R51  4K7  [RES4B]
R65  36K  [0603]
R66  47K  [0603]
R69  1.5K  [0603]
R70  10K  [0603]
R81  0  [0603]
R82  0  [0603]
R95  1M  [0603]
R96  600  [0805]
R97  600  [0805]
R98  600  [0805]
R99  600  [0805]
R126  0  [0805]
R136  50  [0603]
R137  50  [0603]
R138  50  [0603]
RV1  10K  [ADJRH]
T1  9013  [SOT-23]
T2  9013  [SOT-23]
U4  SN65HVD230  [SO8]
U6  M25P64-VME6G  [VDFPN8(8*6)]
U9  STLM75M2F  [SO8]
U11  USBLC6-2P6  [SOT-666]

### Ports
BNC1 (out), BNC2 (out), BNC3 (out), CAN_RX (out), CAN_TX (in), Flash_CS (in), Flash_MISO (out), Flash_MOSI (in), Flash_SCK (in), LED1 (in), LED2 (in), LED3 (in), LED4 (in), Potentiometer (out), TemperatureSensor_INT (out), TemperatureSensor_SCL (bidir), TemperatureSensor_SDA (bidir), USB_Disconnect (in), USB_DM (bidir), USB_DP (bidir)

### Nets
+3V3: C14.2 C27.2 C49.2 R10.1 R27.2 R51.1(R0) R51.3(R2) R51.5(R3) R51.7(R1) R66.2 RV1.3(TOP) T2.3(C) U4.3(VCC) U6.3(~{W}) U6.7(~{HOL}D) U6.8(VCC) U9.8(VDD)
GND: C14.1 C27.1 C49.1 C74.1 C78.1 C100.1 CN2.1 CN2.2 CN2.3 CN2.4 CN3.1 CN3.2 CN3.3 CN3.4 CN4.3 CN4.6 CN5.1 CN5.2 CN5.3 CN5.4 CN14.4(GND) JP8.1 JP14.1 LD1.2(K) LD2.2(K) LD3.2(K) LD4.2(K) R9.1 R26.2 R65.2 R95.1 R136.2 R137.2 R138.2 RV1.1(BOT) T1.1(E) U4.2(GND) U6.4(VSS) U9.4(GND) U9.5(A2) U9.6(A1) U9.7(A0) U11.2(GND)
U5V: C74.2 CN14.1(VCC) R70.1 U11.5(Vbus)
PA11: R81.1 ; port USB_DM
PA12: R82.1 ; port USB_DP
PB8: R32.2 ; port CAN_RX
PB9: U4.1(D) ; port CAN_TX
PB14: JP14.3 ; port USB_Disconnect
PC4: R126.1 ; port Potentiometer
PF6: R96.2 ; port LED1
PF7: R97.2 ; port LED2
PF8: R98.2 ; port LED3
PF9: R99.2 ; port LED4
NetC78_2: C78.2 CN14.0(SHELL) R95.2
NetC100_2: C100.2 R126.2 RV1.2(TAP)
NetCN1_15: CN5.5 JP25.1 ; port BNC1
NetCN1_17: CN3.5 JP24.1 ; port BNC2
NetCN1_19: CN2.5 JP23.1 ; port BNC3
NetCN4_2: CN4.2 JP6.2(NO) U4.6(CANL)
NetCN4_5: CN4.5 R9.2
NetCN4_7: CN4.7 R28.1 U4.7(CANH)
NetCN4_9: CN4.9 R10.2
NetCN14_2: CN14.2(D-) U11.1(I/O1)
NetCN14_3: CN14.3(D+) U11.3(I/O2)
NetJP6_1: JP6.1(COMMON) R28.2
NetJP8_2: JP8.2 R26.1 U4.8(RS)
NetJP8_3: JP8.3 R27.1
NetJP11_2: R46.2 ; port TemperatureSensor_INT
NetJP14_2: JP14.2 R66.1 T1.2(B)
NetJP23_2: JP23.2 R136.1
NetJP24_2: JP24.2 R137.1
NetJP25_2: JP25.2 R138.1
NetLD1_1: LD1.1(A) R96.1
NetLD2_1: LD2.1(A) R97.1
NetLD3_1: LD3.1(A) R98.1
NetLD4_1: LD4.1(A) R99.1
NetR32_1: R32.1 U4.4(R)
NetR35_1: R35.1 U6.1(~{S})
NetR35_2: R35.2 ; port Flash_CS
NetR37_1: R37.1 ; port Flash_MISO
NetR37_2: R37.2 U6.2(Q)
NetR38_1: R38.1 R51.4(R3) U9.1(SDA)
NetR38_2: R38.2 ; port TemperatureSensor_SDA
NetR44_1: R44.1 R51.6(R2) U9.2(SCL)
NetR44_2: R44.2 ; port TemperatureSensor_SCL
NetR46_1: R46.1 R51.8(R0) U9.3(~{OS}/INT)
NetR65_1: R65.1 R70.2 T1.3(C) T2.2(B)
NetR69_1: R69.1 T2.1(E)
NetR69_2: R69.2 R82.2 U11.4(I/O2)
NetR81_2: R81.2 U11.6(I/O1)
NetU6_5: U6.5(D) ; port Flash_MOSI
NetU6_6: U6.6(C) ; port Flash_SCK

Not connected (* = marked no-connect by the designer): CN4 1* 4* 8*; R51 2(R1)*; U4 5(Vref)*

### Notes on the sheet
- (near R96) PF6
- PA12
- PA11
- (near R97) PF7
- (near R98) PF8
- (near R99) PF9
- LED
- (near JP14) PB14
- USB
- JP23-25 Default setting:open
- PC2
- PC1
- PC4
- (near R32) PB9
- (near R27) Default setting: 1<->2
- (near CN4) Default setting: Open
- (near CN2) PC3
- (near R32) PB8
- BNC connector
- Potentiometer
- CAN
- PB2
- PA6
- PA5
- PA7
- PB6
- PB7
- PB5
- SPI Flash
- Temperature sensor

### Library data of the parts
C14 C27 C74 = CAP: Capacitor
C49 = cap: Capacitor; Value: 100pF
C78 C100 = CAP: Capacitor; Value: 100pF
CN2 CN3 CN5 = Header 5: Header, 5-Pin
CN4 = DB9
CN14 = USB-B
JP6 = JP2
JP8 JP14 = Jumper3
JP23-JP25 = Circuit Breaker
LD1-LD4 = LED2: Typical RED, GREEN, YELLOW, AMBER GaAs LED
R9 R10 R26-R28 = res1: Resistor; Value: 1K
R32 R35 R37 R38 R44 R46 R66 R81 R82 R95-R99 R126 R136-R138 = Res1: Resistor; Value: 1K
R51 = RES4B
R65 R70 = R: Right: 20; Bottom: 30
R69 = RES1
RV1 = RV
T1 T2 = NPN
U4 = SN65HVD230D
U9 = STLM75DW2F
U11 = USBLC6-2

## Sheet MotorCtrl.SchDoc: STM3210E-EVAL Motor Control
size A4; Date: Not used; ApprovedBy: Not used; CheckedBy: Not used; Author: Not used; CompanyName: STMicroelectronics; DrawnBy: Not used; Engineer: Not used; Organization: Not used; Address1: Not used; Address2: Not used; Address3: Not used; Address4: Not used; DocumentNumber: Not used; Revision: Not used; SheetNumber: 9; SheetTotal: 12
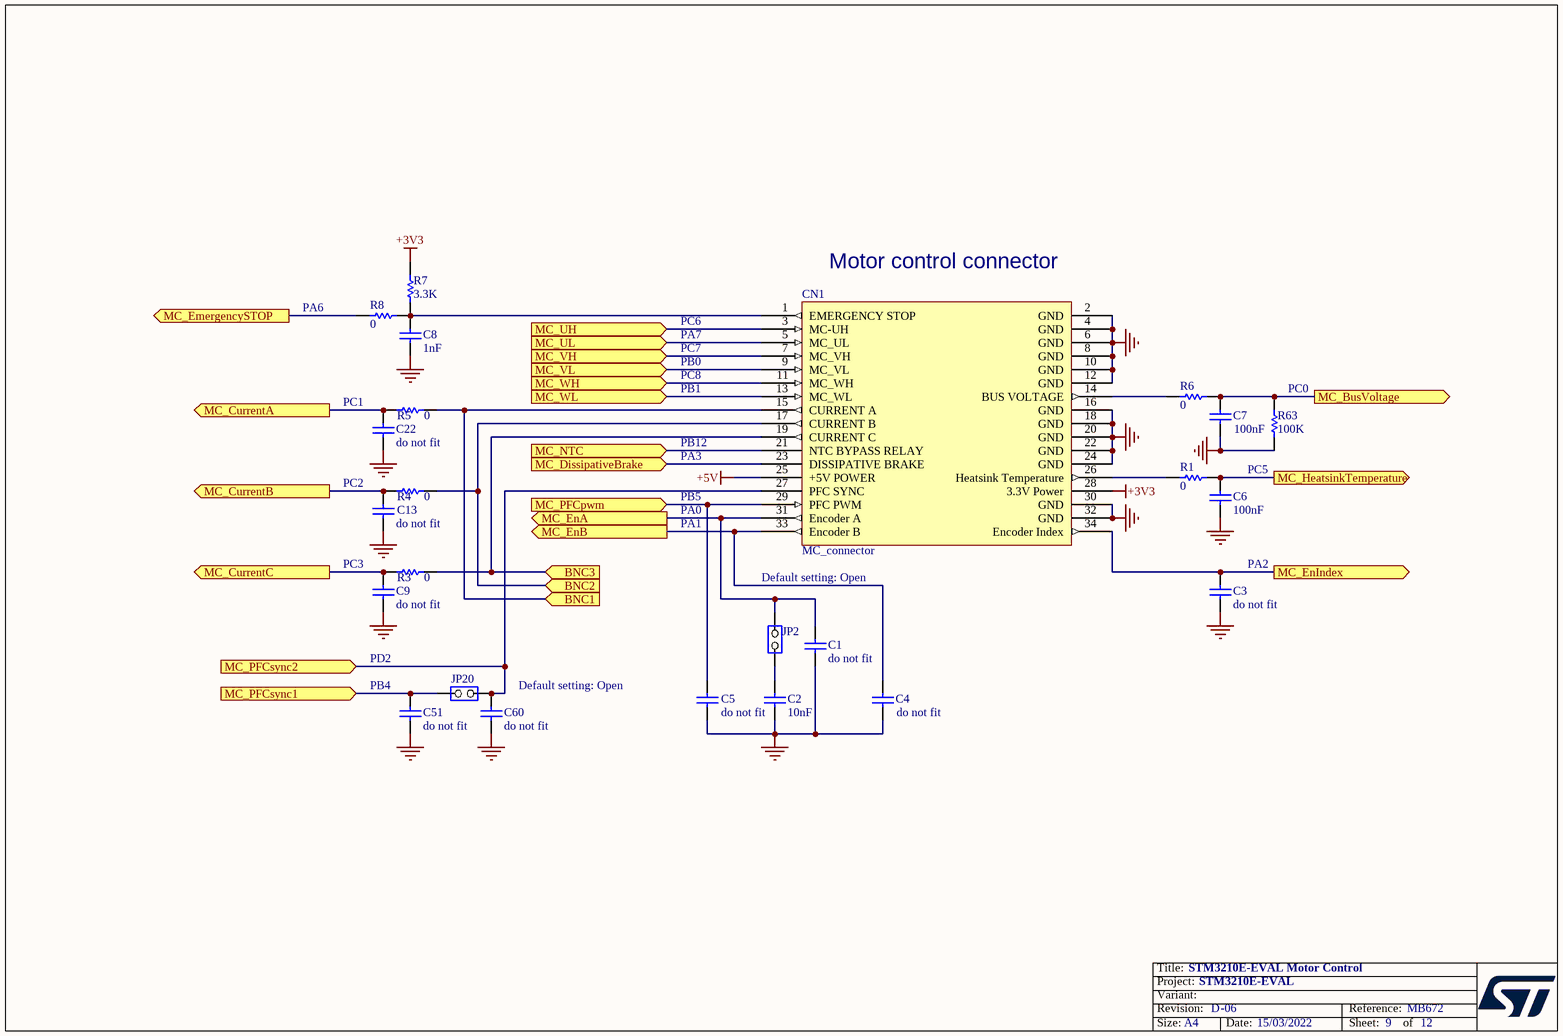
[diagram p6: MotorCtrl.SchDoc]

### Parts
C1  do not fit  [0603]
C2  10nF  [0603]
C3  do not fit  [0603]
C4  do not fit  [0603]
C5  do not fit  [0603]
C6  100nF  [0603]
C7  100nF  [0603]
C8  1nF  [0603]
C9  do not fit  [0603]
C13  do not fit  [0603]
C22  do not fit  [0603]
C51  do not fit  [0603]
C60  do not fit  [0603]
CN1  MC_connector  [IDC34S]
JP2  (no value)  [SIP2]
JP20  (no value)  [SIP2]
R1  0  [0603]
R3  0  [0603]
R4  0  [0603]
R5  0  [0603]
R6  0  [0603]
R7  3.3K  [0603]
R8  0  [0805]
R63  100K  [0603]

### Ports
BNC1 (in), BNC2 (in), BNC3 (in), MC_BusVoltage (out), MC_CurrentA (out), MC_CurrentB (out), MC_CurrentC (out), MC_DissipativeBrake (in), MC_EmergencySTOP (out), MC_EnA (out), MC_EnB (out), MC_EnIndex (out), MC_HeatsinkTemperature (out), MC_NTC (in), MC_PFCpwm (in), MC_PFCsync1 (in), MC_PFCsync2 (in), MC_UH (in), MC_UL (in), MC_VH (in), MC_VL (in), MC_WH (in), MC_WL (in)

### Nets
+3V3: CN1.28(3.3V_Power) R7.2
+5V: CN1.25(+5V_POWER)
GND: C1.1 C2.1 C3.1 C4.1 C5.1 C6.1 C7.1 C8.1 C9.1 C13.1 C22.1 C51.1 C60.1 CN1.2(GND) CN1.4(GND) CN1.6(GND) CN1.8(GND) CN1.10(GND) CN1.12(GND) CN1.16(GND) CN1.18(GND) CN1.20(GND) CN1.22(GND) CN1.24(GND) CN1.30(GND) CN1.32(GND) R63.1
PA1: C4.2 CN1.33(Encoder_B) ; port MC_EnB
PA2: C3.2 CN1.34(Encoder_Index) ; port MC_EnIndex
PA7: CN1.5(MC_UL) ; port MC_UL
PB0: CN1.9(MC_VL) ; port MC_VL
PB1: CN1.13(MC_WL) ; port MC_WL
PB4: C51.2 JP20.2(NO) ; port MC_PFCsync1
PB5: C5.2 CN1.29(PFC_PWM) ; port MC_PFCpwm
PB12: CN1.21(NTC_BYPASS_RELAY) ; port MC_NTC
PC0: C7.2 R6.2 R63.2 ; port MC_BusVoltage
PC1: C22.2 R5.1 ; port MC_CurrentA
PC2: C13.2 R4.1 ; port MC_CurrentB
PC3: C9.2 R3.1 ; port MC_CurrentC
PC5: C6.2 R1.2 ; port MC_HeatsinkTemperature
PC6: CN1.3(MC-UH) ; port MC_UH
PC7: CN1.7(MC_VH) ; port MC_VH
PC8: CN1.11(MC_WH) ; port MC_WH
PD2: C60.2 CN1.27(PFC_SYNC) JP20.1(COMMON) ; port MC_PFCsync2
NetC1_2: C1.2 CN1.31(Encoder_A) JP2.1(COMMON) ; port MC_EnA
NetC2_2: C2.2 JP2.2(NO)
NetC8_2: C8.2 CN1.1(EMERGENCY_STOP) R7.1 R8.1
NetCN1_14: CN1.14(BUS_VOLTAGE) R6.1
NetCN1_15: CN1.15(CURRENT_A) R5.2 ; port BNC1
NetCN1_17: CN1.17(CURRENT_B) R4.2 ; port BNC2
NetCN1_19: CN1.19(CURRENT_C) R3.2 ; port BNC3
NetCN1_23: CN1.23(DISSIPATIVE_BRAKE) ; port MC_DissipativeBrake
NetCN1_26: CN1.26(Heatsink_Temperature) R1.1
NetJP3_2: R8.2 ; port MC_EmergencySTOP

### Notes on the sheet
- (near R8) PA6
- (near CN1) Motor control connector
- PC6
- PA7
- PC7
- PB0
- PC8
- PC1
- PB1
- PB12
- (near R63) PC0
- PC2
- PA3
- PA0
- PB5
- PC5
- PC3
- PA1
- Default setting: Open
- (near C3) PA2
- (near C51) PB4
- PD2
- (near C60) Default setting: Open

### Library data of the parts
C1-C7 C9 C13 C22 C51 C60 = cap: Capacitor; Value: 100pF
C8 = CAP: Capacitor; Value: 100pF
JP2 JP20 = JP2
R1 R3-R8 R63 = Res1: Resistor; Value: 1K

## Sheet Power.SchDoc: STM3210E-EVAL Power
size A4; Date: Not used; ApprovedBy: Not used; CheckedBy: Not used; Author: Not used; CompanyName: STMicroelectronics; DrawnBy: Not used; Engineer: Not used; Organization: Not used; Address1: Not used; Address2: Not used; Address3: Not used; Address4: Not used; DocumentNumber: Not used; Revision: Not used; SheetNumber: 10; SheetTotal: 12
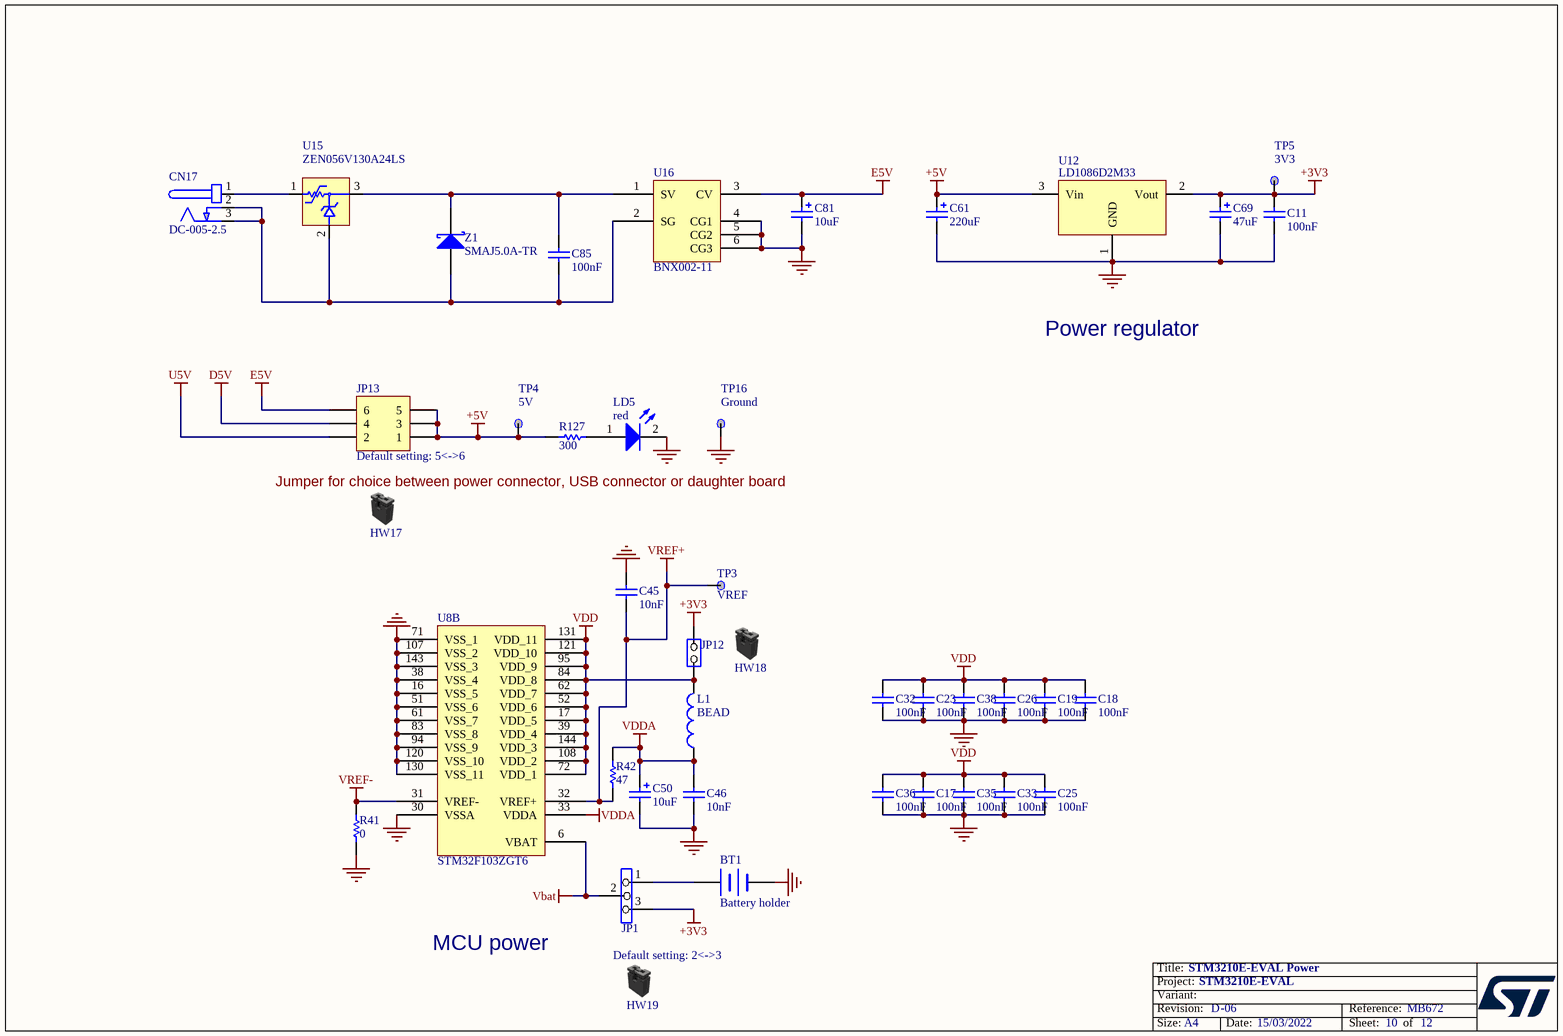
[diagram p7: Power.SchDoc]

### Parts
BT1  Battery holder  [BATT]
C11  100nF  [0603P]
C17  100nF  [0603P]
C18  100nF  [0603P]
C19  100nF  [0603P]
C23  100nF  [0603P]
C25  100nF  [0603P]
C26  100nF  [0603P]
C32  100nF  [0603P]
C33  100nF  [0603P]
C35  100nF  [0603P]
C36  100nF  [0603P]
C38  100nF  [0603P]
C45  10nF  [0603]
C46  10nF  [0603]
C50  10uF  [TAN-B]
C61  220uF  [C310M]
C69  47uF  [TAN-B]
C81  10uF  [C160M]
C85  100nF  [0603P]
CN17  DC-005-2.5  [DC10B]
HW17  Shunt Black 2.54mm  (value not drawn)  (mechanical)
HW18  Shunt Black 2.54mm  (value not drawn)  (mechanical)
HW19  Shunt Black 2.54mm  (value not drawn)  (mechanical)
JP1  (no value)  [SIP3]
JP12  (no value)  [SIP2]
JP13  (no value)  [2*3P]
L1  BEAD  [0603]
LD5  red  [D0603]
R41  0  [0805]
R42  47  [0805]
R127  300  [0603]
TP3  VREF  [TP]
TP4  5V  [TP]
TP5  3V3  [TP]
TP16  Ground  [TP]
U8  STM32F103ZGT6  (part B of 2)
U12  LD1086D2M33  [D2PAK/A]
U15  ZEN056V130A24LS  [polyzen]
U16  BNX002-11  [BNX001]
Z1  SMAJ5.0A-TR  [1R1C]

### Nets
+3V3: C11.1 C69.1 JP1.3 JP12.2(NO) TP5.1 U12.2(Vout)
+5V: C61.1 JP13.1 JP13.3 JP13.5 R127.2 TP4.1 U12.3(Vin)
D5V: JP13.4
E5V: C81.1 JP13.6 U16.3(CV)
GND: BT1.2(-) C11.2 C17.2 C18.2 C19.2 C23.2 C25.2 C26.2 C32.2 C33.2 C35.2 C36.2 C38.2 C45.2 C46.1 C50.2 C61.2 C69.2 C81.2 LD5.2(K) R41.2 TP16.1 U8.16(VSS_5) U8.30(VSSA) U8.38(VSS_4) U8.51(VSS_6) U8.61(VSS_7) U8.71(VSS_1) U8.83(VSS_8) U8.94(VSS_9) U8.107(VSS_2) U8.120(VSS_10) U8.130(VSS_11) U8.143(VSS_3) U12.1(GND) U16.4(CG1) U16.5(CG2) U16.6(CG3)
U5V: JP13.2
Vbat: JP1.2 U8.6(VBAT)
VDD: C17.1 C18.1 C19.1 C23.1 C25.1 C26.1 C32.1 C33.1 C35.1 C36.1 C38.1 JP12.1(COMMON) L1.2 U8.17(VDD_5) U8.39(VDD_4) U8.52(VDD_6) U8.62(VDD_7) U8.72(VDD_1) U8.84(VDD_8) U8.95(VDD_9) U8.108(VDD_2) U8.121(VDD_10) U8.131(VDD_11) U8.144(VDD_3)
VDDA: C46.2 C50.1 L1.1 R42.2 U8.33(VDDA)
VREF+: C45.1 R42.1 TP3.1 U8.32(VREF+)
VREF-: R41.1 U8.31(VREF-)
NetBT1_1: BT1.1(+) JP1.1
NetC85_1: C85.1 U15.3 U16.1(SV) Z1.2(K)
NetC85_2: C85.2 CN17.2(GND) CN17.3(GND) U15.2 U16.2(SG) Z1.1(A)
NetCN17_1: CN17.1(+) U15.1
NetLD5_1: LD5.1(A) R127.1

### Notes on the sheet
- Power regulator
- (near HW17) Jumper for choice between power connector, USB connector or daughter board
- (near JP13) Default setting: 5<->6
- MCU power
- (near HW19) Default setting: 2<->3

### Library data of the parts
BT1 = BATTERY
C11 = Cap: Capacitor; Value: 10nF
C17-C19 C23 C25 C26 C32 C33 C35 C36 C38 = CAP: Capacitor
C45 C46 = Cap: Capacitor
C50 = Cap Pol1: Polarized Capacitor (Radial)
C61 C69 = Cap Pol1: Polarized Capacitor (Radial); Value: 10uF
C81 = Cap Pol1: as C53 on sheet Audio
C85 = CAP: Capacitor; Value: 100pF
CN17 = PJ202A
JP1 = Jumper3
JP12 = JP2
JP13 = Header 3X2: Header, 3-Pin, Dual row
L1 = Inductor: Value: 100uH
LD5 = LED2: as LD1 on sheet Peripherals
R41 R42 = Res1: Resistor; Value: 1K
R127 = res1: Resistor; Value: 1K
TP3-TP5 TP16 = TP
U8 = BigPiranha_new
U12 = VOLTREG1
U16 = BNX002
Z1 = D Schottky: Schottky Diode; Code - JEDEC: DO-214-AA

## Sheet JTAG&SWD.SchDoc: STM3210E-EVAL JTAG&Trace
size A4; Date: Not used; ApprovedBy: Not used; CheckedBy: Not used; Author: Not used; CompanyName: STMicroelectronics; DrawnBy: Not used; Engineer: Not used; Organization: Not used; Address1: Not used; Address2: Not used; Address3: Not used; Address4: Not used; DocumentNumber: Not used; Revision: Not used; SheetNumber: 12; SheetTotal: 12
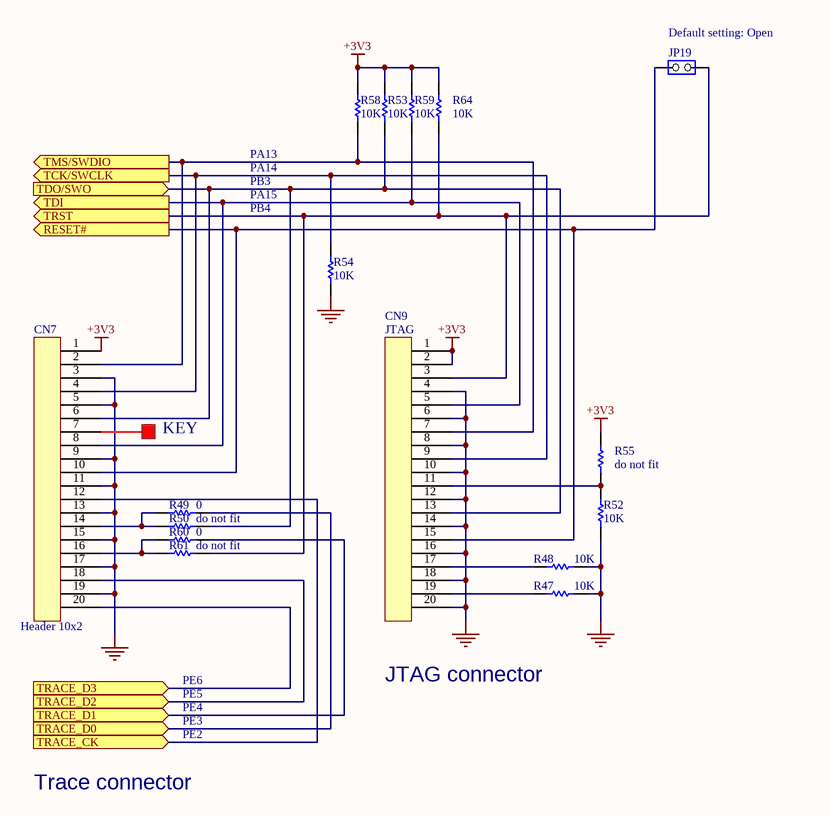
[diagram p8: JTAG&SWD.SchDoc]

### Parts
CN7  Header 10x2  [IDC20S]
CN9  JTAG  [IDC20S]
JP19  (no value)  [SIP2]
R47  10K  [0603]
R48  10K  [0603]
R49  0  [0603]
R50  do not fit  [0603]
R52  10K  [0603]
R53  10K  [0603]
R54  10K  [0603]
R55  do not fit  [0603]
R58  10K  [0603]
R59  10K  [0603]
R60  0  [0603]
R61  do not fit  [0603]
R64  10K  [0603]

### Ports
RESET# (out), TCK/SWCLK (out), TDI (out), TDO/SWO (in), TMS/SWDIO (out), TRACE_CK (in), TRACE_D0 (in), TRACE_D1 (in), TRACE_D2 (in), TRACE_D3 (in), TRST (out)

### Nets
+3V3: CN7.1 CN9.1 CN9.2 R53.2 R55.2 R58.2 R59.2 R64.2
GND: CN7.3 CN7.5 CN7.9 CN7.11 CN7.13 CN7.15 CN7.17 CN7.19 CN9.4 CN9.6 CN9.8 CN9.10 CN9.12 CN9.14 CN9.16 CN9.18 CN9.20 R47.2 R48.2 R52.1 R54.1
A19: R49.2 ; port TRACE_D0
A20: R60.2 ; port TRACE_D1
A21: CN7.18 ; port TRACE_D2
A22: CN7.20 ; port TRACE_D3
A23: CN7.12 ; port TRACE_CK
PA13: CN7.2 CN9.7 R58.1 ; port TMS/SWDIO
PA14: CN7.4 CN9.9 R54.2 ; port TCK/SWCLK
PA15: CN7.8 CN9.5 R59.1 ; port TDI
PB3: CN7.6 CN9.13 R50.2 R53.1 ; port TDO/SWO
PB4: CN9.3 JP19.1(COMMON) R61.2 R64.1 ; port TRST
RESET#: CN7.10 CN9.15 JP19.2(NO) ; port RESET#
NetCN7_14: CN7.14 R49.1 R50.1
NetCN7_16: CN7.16 R60.1 R61.1
NetCN9_11: CN9.11 R52.2 R55.1
NetCN9_17: CN9.17 R48.1
NetCN9_19: CN9.19 R47.1

Not connected (* = marked no-connect by the designer): CN7 7

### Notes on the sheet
- (near JP19) Default setting: Open
- PA14
- PA13
- PB4
- PB3
- PA15
- KEY
- PE4
- PE5
- PE6
- JTAG connector
- PE2
- PE3
- Trace connector

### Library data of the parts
CN7 CN9 = 20PIN1
JP19 = JP2
R47-R50 R52-R55 R58-R61 R64 = Res1: Resistor; Value: 1K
